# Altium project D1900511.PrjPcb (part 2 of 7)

## Sheet ISC_C3_SH3.SchDoc: ISC System Wiring Diagram
size B; DrawnBy: Filiberto Clara; Engineer: Filiberto Clara; Organization: LIGO Laboratory; Address1: California Institute of Technology; Address2: Massachusetts Institute of Technology; DocumentNumber: D1900511; Revision: V11; SheetNumber: 7; SheetTotal: 39
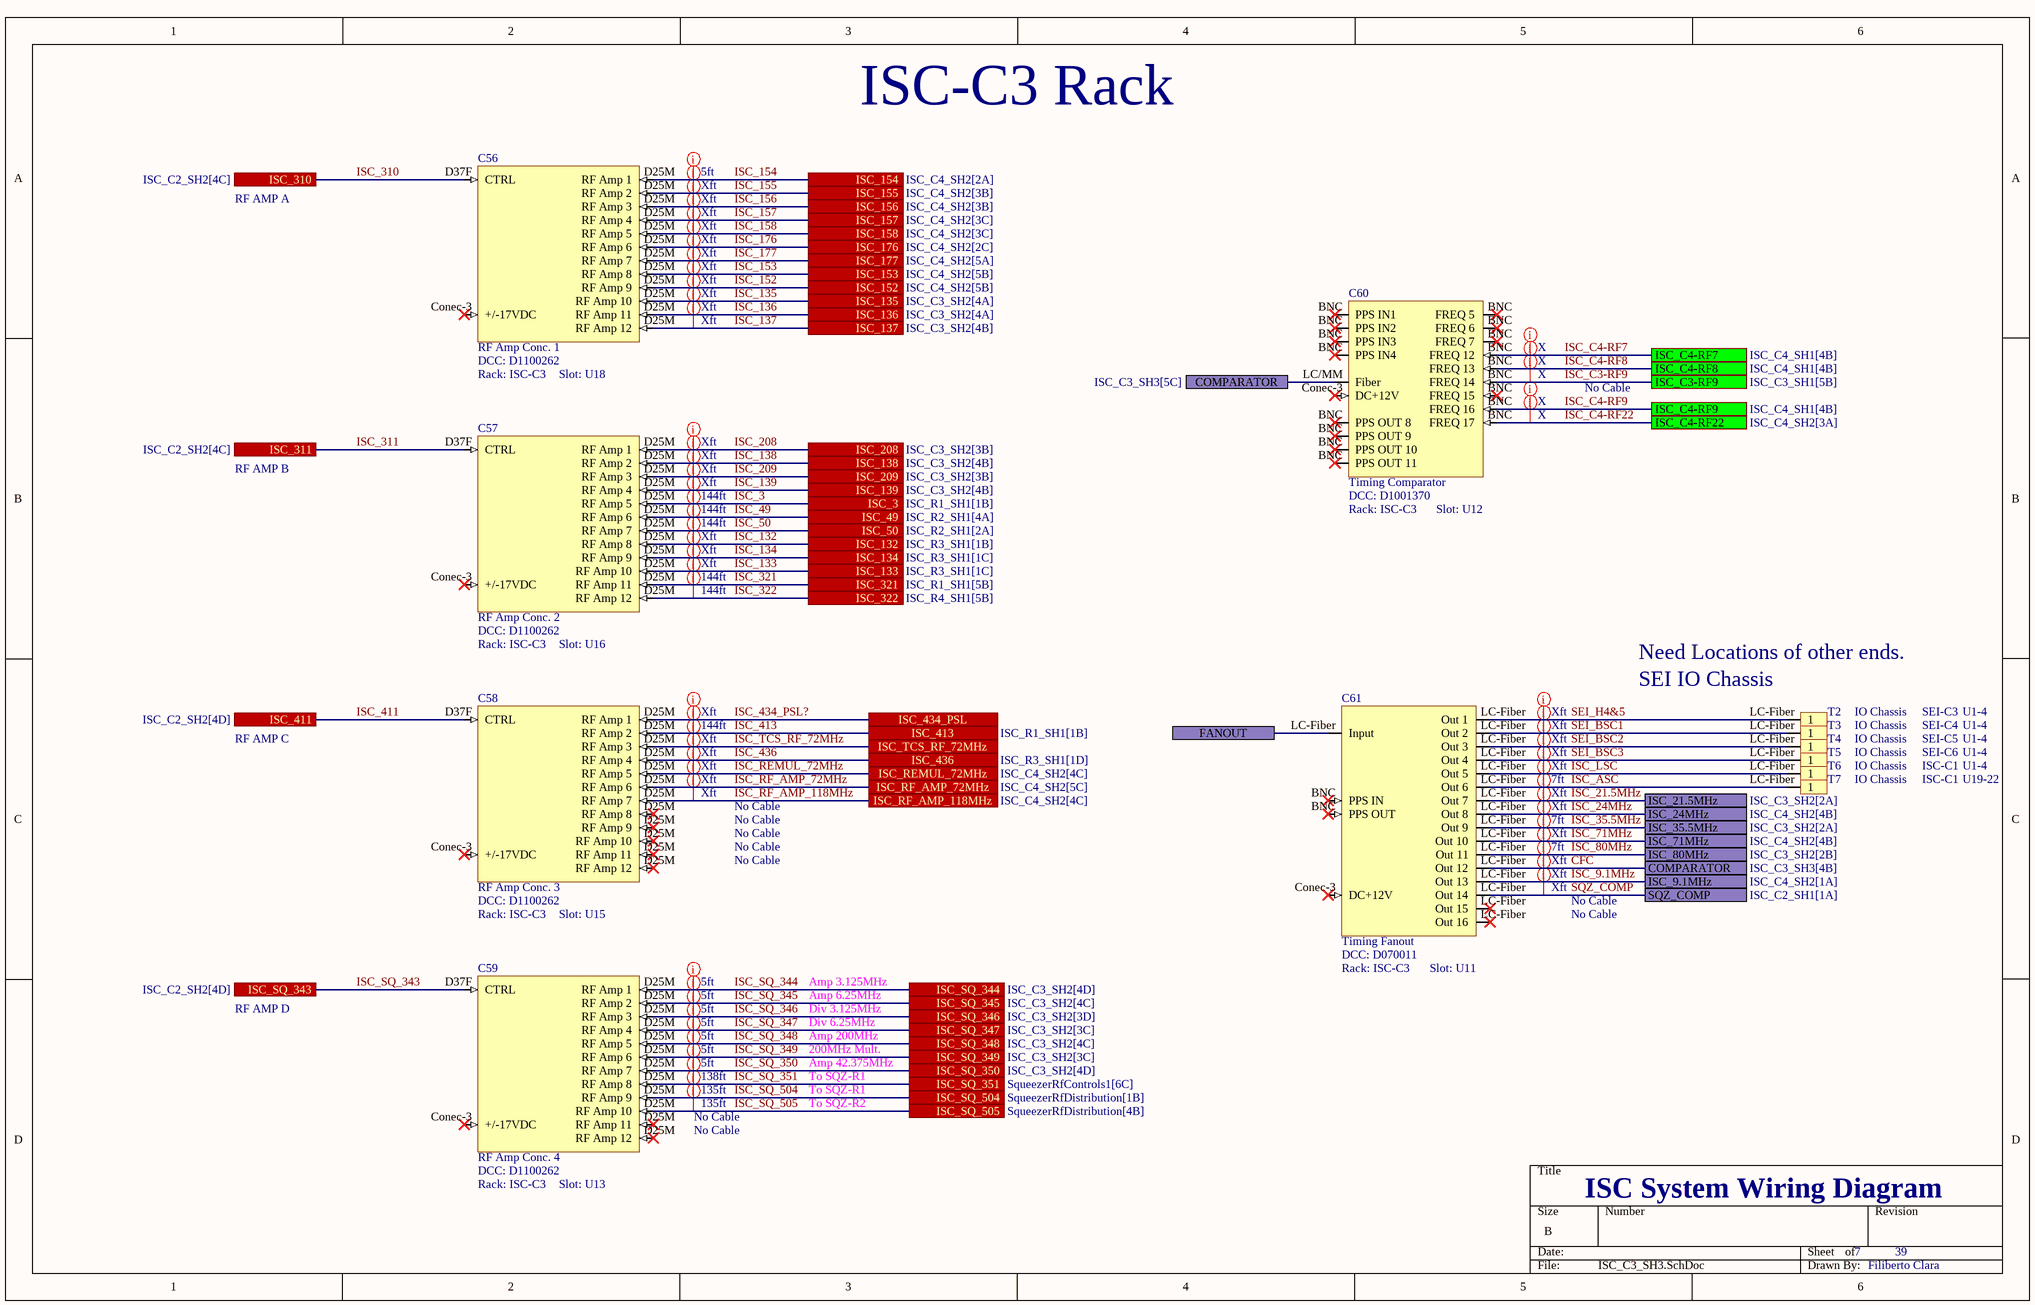
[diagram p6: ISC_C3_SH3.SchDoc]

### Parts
C56  RF Amp Conc. 1  DCC: D1100262  Rack: ISC-C3  Slot: U18
C57  RF Amp Conc. 2  DCC: D1100262  Rack: ISC-C3  Slot: U16
C58  RF Amp Conc. 3  DCC: D1100262  Rack: ISC-C3  Slot: U15
C59  RF Amp Conc. 4  DCC: D1100262  Rack: ISC-C3  Slot: U13
C60  Timing Comparator  DCC: D1001370  Rack: ISC-C3  Slot: U12
C61  Timing Fanout  DCC: D070011  Rack: ISC-C3  Slot: U11
T2  IO Chassis  Rack: SEI-C3  Slot: U1-4
T3  IO Chassis  Rack: SEI-C4  Slot: U1-4
T4  IO Chassis  Rack: SEI-C5  Slot: U1-4
T5  IO Chassis  Rack: SEI-C6  Slot: U1-4
T6  IO Chassis  Rack: ISC-C1  Slot: U1-4
T7  IO Chassis  Rack: ISC-C1  Slot: U19-22

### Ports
COMPARATOR (see ISC_C3_SH3[4B]), COMPARATOR (see ISC_C3_SH3[5C]), FANOUT, ISC_3 (see ISC_R1_SH1[1B]), ISC_9.1MHz (see ISC_C4_SH2[1A]), ISC_21.5MHz (see ISC_C3_SH2[2A]), ISC_24MHz (see ISC_C4_SH2[4B]), ISC_35.5MHz (see ISC_C3_SH2[2A]), ISC_49 (see ISC_R2_SH1[4A]), ISC_50 (see ISC_R2_SH1[2A]), ISC_71MHz (see ISC_C4_SH2[4B]), ISC_80MHz (see ISC_C3_SH2[2B]), ISC_132 (see ISC_R3_SH1[1B]), ISC_133 (see ISC_R3_SH1[1C]), ISC_134 (see ISC_R3_SH1[1C]), ISC_135 (see ISC_C3_SH2[4A]), ISC_136 (see ISC_C3_SH2[4A]), ISC_137 (see ISC_C3_SH2[4B]), ISC_138 (see ISC_C3_SH2[4B]), ISC_139 (see ISC_C3_SH2[4B]), ISC_152 (see ISC_C4_SH2[5B]), ISC_153 (see ISC_C4_SH2[5B]), ISC_154 (see ISC_C4_SH2[2A]), ISC_155 (see ISC_C4_SH2[3B]), ISC_156 (see ISC_C4_SH2[3B]), ISC_157 (see ISC_C4_SH2[3C]), ISC_158 (see ISC_C4_SH2[3C]), ISC_176 (see ISC_C4_SH2[2C]), ISC_177 (see ISC_C4_SH2[5A]), ISC_208 (see ISC_C3_SH2[3B]), ISC_209 (see ISC_C3_SH2[3B]), ISC_310 (see ISC_C2_SH2[4C]), ISC_311 (see ISC_C2_SH2[4C]), ISC_321 (see ISC_R1_SH1[5B]), ISC_322 (see ISC_R4_SH1[5B]), ISC_411 (see ISC_C2_SH2[4D]), ISC_413 (see ISC_R1_SH1[1B]), ISC_434_PSL, ISC_436 (see ISC_R3_SH1[1D]), ISC_C3-RF9 (see ISC_C3_SH1[5B]), ISC_C4-RF7 (see ISC_C4_SH1[4B]), ISC_C4-RF8 (see ISC_C4_SH1[4B]), ISC_C4-RF9 (see ISC_C4_SH1[4B]), ISC_C4-RF22 (see ISC_C4_SH2[3A]), ISC_REMUL_72MHz (see ISC_C4_SH2[4C]), ISC_RF_AMP_72MHz (see ISC_C4_SH2[5C]), ISC_RF_AMP_118MHz (see ISC_C4_SH2[4C]), ISC_SQ_343 (see ISC_C2_SH2[4D]), ISC_SQ_344 (see ISC_C3_SH2[4D]), ISC_SQ_345 (see ISC_C3_SH2[4C]), ISC_SQ_346 (see ISC_C3_SH2[3D]), ISC_SQ_347 (see ISC_C3_SH2[3C]), ISC_SQ_348 (see ISC_C3_SH2[4C]), ISC_SQ_349 (see ISC_C3_SH2[3C]), ISC_SQ_350 (see ISC_C3_SH2[4D]), ISC_SQ_351 (see SqueezerRfControls1[6C]), ISC_SQ_504 (see SqueezerRfDistribution[1B]), ISC_SQ_505 (see SqueezerRfDistribution[4B]), ISC_TCS_RF_72MHz, SQZ_COMP (see ISC_C2_SH1[1A])

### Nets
CFC: C60.LC/MM(Fiber) C61.LC-Fiber(Out_12) ; port COMPARATOR
ISC_3: C57.D25M(RF_Amp_5) ; port ISC_3
ISC_9.1MHz: C61.LC-Fiber(Out_13) ; port ISC_9.1MHz
ISC_21.5MHz: C61.LC-Fiber(Out_7) ; port ISC_21.5MHz
ISC_24MHz: C61.LC-Fiber(Out_8) ; port ISC_24MHz
ISC_35.5MHz: C61.LC-Fiber(Out_9) ; port ISC_35.5MHz
ISC_49: C57.D25M(RF_Amp_6) ; port ISC_49
ISC_50: C57.D25M(RF_Amp_7) ; port ISC_50
ISC_71MHz: C61.LC-Fiber(Out_10) ; port ISC_71MHz
ISC_80MHz: C61.LC-Fiber(Out_11) ; port ISC_80MHz
ISC_132: C57.D25M(RF_Amp_8) ; port ISC_132
ISC_133: C57.D25M(RF_Amp_10) ; port ISC_133
ISC_134: C57.D25M(RF_Amp_9) ; port ISC_134
ISC_135: C56.D25M(RF_Amp_10) ; port ISC_135
ISC_136: C56.D25M(RF_Amp_11) ; port ISC_136
ISC_137: C56.D25M(RF_Amp_12) ; port ISC_137
ISC_138: C57.D25M(RF_Amp_2) ; port ISC_138
ISC_139: C57.D25M(RF_Amp_4) ; port ISC_139
ISC_152: C56.D25M(RF_Amp_9) ; port ISC_152
ISC_153: C56.D25M(RF_Amp_8) ; port ISC_153
ISC_154: C56.D25M(RF_Amp_1) ; port ISC_154
ISC_155: C56.D25M(RF_Amp_2) ; port ISC_155
ISC_156: C56.D25M(RF_Amp_3) ; port ISC_156
ISC_157: C56.D25M(RF_Amp_4) ; port ISC_157
ISC_158: C56.D25M(RF_Amp_5) ; port ISC_158
ISC_176: C56.D25M(RF_Amp_6) ; port ISC_176
ISC_177: C56.D25M(RF_Amp_7) ; port ISC_177
ISC_208: C57.D25M(RF_Amp_1) ; port ISC_208
ISC_209: C57.D25M(RF_Amp_3) ; port ISC_209
ISC_310: C56.D37F(CTRL) ; port ISC_310
ISC_311: C57.D37F(CTRL) ; port ISC_311
ISC_321: C57.D25M(RF_Amp_11) ; port ISC_321
ISC_322: C57.D25M(RF_Amp_12) ; port ISC_322
ISC_411: C58.D37F(CTRL) ; port ISC_411
ISC_413: C58.D25M(RF_Amp_2) ; port ISC_413
ISC_434_PSL?: C58.D25M(RF_Amp_1) ; port ISC_434_PSL
ISC_436: C58.D25M(RF_Amp_4) ; port ISC_436
ISC_ASC: C61.LC-Fiber(Out_6) T7.LC-Fiber(1)
ISC_C3-RF9: C60.BNC(FREQ_14) ; port ISC_C3-RF9
ISC_C4-RF7: C60.BNC(PPS_IN1) ; port ISC_C4-RF7
ISC_C4-RF8: C60.BNC(FREQ_13) ; port ISC_C4-RF8
ISC_C4-RF9: C60.BNC(FREQ_16) ; port ISC_C4-RF9
ISC_C4-RF22: C60.BNC(FREQ_17) ; port ISC_C4-RF22
ISC_LSC: C61.LC-Fiber(Out_5) T6.LC-Fiber(1)
ISC_REMUL_72MHz: C58.D25M(RF_Amp_5) ; port ISC_REMUL_72MHz
ISC_RF_AMP_72MHz: C58.D25M(RF_Amp_6) ; port ISC_RF_AMP_72MHz
ISC_RF_AMP_118MHz: C58.D25M(RF_Amp_7) ; port ISC_RF_AMP_118MHz
ISC_SQ_343: C59.D37F(CTRL) ; port ISC_SQ_343
ISC_SQ_344: C59.D25M(RF_Amp_1) ; port ISC_SQ_344
ISC_SQ_345: C59.D25M(RF_Amp_2) ; port ISC_SQ_345
ISC_SQ_346: C59.D25M(RF_Amp_3) ; port ISC_SQ_346
ISC_SQ_347: C59.D25M(RF_Amp_4) ; port ISC_SQ_347
ISC_SQ_348: C59.D25M(RF_Amp_5) ; port ISC_SQ_348
ISC_SQ_349: C59.D25M(RF_Amp_6) ; port ISC_SQ_349
ISC_SQ_350: C59.D25M(RF_Amp_7) ; port ISC_SQ_350
ISC_SQ_351: C59.D25M(RF_Amp_8) ; port ISC_SQ_351
ISC_SQ_504: C59.D25M(RF_Amp_9) ; port ISC_SQ_504
ISC_SQ_505: C59.D25M(RF_Amp_10) ; port ISC_SQ_505
ISC_TCS_RF_72MHz: C58.D25M(RF_Amp_3) ; port ISC_TCS_RF_72MHz
SEI_BSC1: C61.LC-Fiber(Out_2) T3.LC-Fiber(1)
SEI_BSC2: C61.LC-Fiber(Out_3) T4.LC-Fiber(1)
SEI_BSC3: C61.LC-Fiber(Out_4) T5.LC-Fiber(1)
SEI_H4&5: C61.LC-Fiber(Out_1) T2.LC-Fiber(1)
SQZ_COMP: C61.LC-Fiber(Out_14) ; port SQZ_COMP
NetC61_LC-Fiber: C61.LC-Fiber(Input) ; port FANOUT

Not connected (* = marked no-connect by the designer): C56 Conec-3(+/-17VDC)*; C57 Conec-3(+/-17VDC)*; C58 Conec-3(+/-17VDC)*; C59 Conec-3(+/-17VDC)*; C60 Conec-3(DC+12V)*; C61 BNC(PPS_IN)* Conec-3(DC+12V)*

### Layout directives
Length: 5ft: ISC_154, ISC_SQ_344, ISC_SQ_345, ISC_SQ_346, ISC_SQ_347, ISC_SQ_348, ISC_SQ_349, ISC_SQ_350
Length: 138ft: ISC_SQ_351
Length: Xft: CFC, ISC_9.1MHz, ISC_21.5MHz, ISC_24MHz, ISC_71MHz, ISC_132, ISC_133, ISC_134, ISC_135, ISC_136, ISC_137, ISC_138, ISC_139, ISC_152, ISC_153, ISC_155, ISC_156, ISC_157, ISC_158, ISC_176, ISC_177, ISC_208, ISC_209, ISC_434_PSL?, ISC_436, ISC_LSC, ISC_REMUL_72MHz, ISC_RF_AMP_72MHz, ISC_RF_AMP_118MHz, ISC_TCS_RF_72MHz, SEI_BSC1, SEI_BSC2, SEI_BSC3, SEI_H4&5, SQZ_COMP
Length: 144ft: ISC_3, ISC_49, ISC_50, ISC_321, ISC_322, ISC_413
Length: 7ft: ISC_35.5MHz, ISC_80MHz, ISC_ASC
Length: X: ISC_C3-RF9, ISC_C4-RF7, ISC_C4-RF8, ISC_C4-RF9, ISC_C4-RF22
Length: 135ft: ISC_SQ_504, ISC_SQ_505

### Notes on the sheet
- ISC-C3 Rack
- RF AMP A
- No Cable
- RF AMP B
- SEI IO Chassis
- Need Locations of other ends.
- RF AMP C
- Amp 3.125MHz
- RF AMP D
- Amp 6.25MHz
- Div 3.125MHz
- Div 6.25MHz
- Amp 200MHz
- 200MHz Mult.
- Amp 42.375MHz
- To SQZ-R1
- To SQZ-R2

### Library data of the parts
C56-C59 = RF Amp Conc.: Serial: Sxxxxxxx; System: ISC
C60 = Timing Comparator: Serial: Sxxxxxxx; System: ISC
C61 = Timing Fanout: Serial: Sxxxxxxx; System: ISC
T2-T7 = Placeholder: Serial: Sxxxxxxx; System: ISC; DCC: tbd

## Sheet ISC_C4_SH1.SchDoc: ISC System Wiring Diagram
size B; DrawnBy: Filiberto Clara; Engineer: Filiberto Clara; Organization: LIGO Laboratory; Address1: California Institute of Technology; Address2: Massachusetts Institute of Technology; DocumentNumber: D1900511; Revision: V11; SheetNumber: 8; SheetTotal: 39
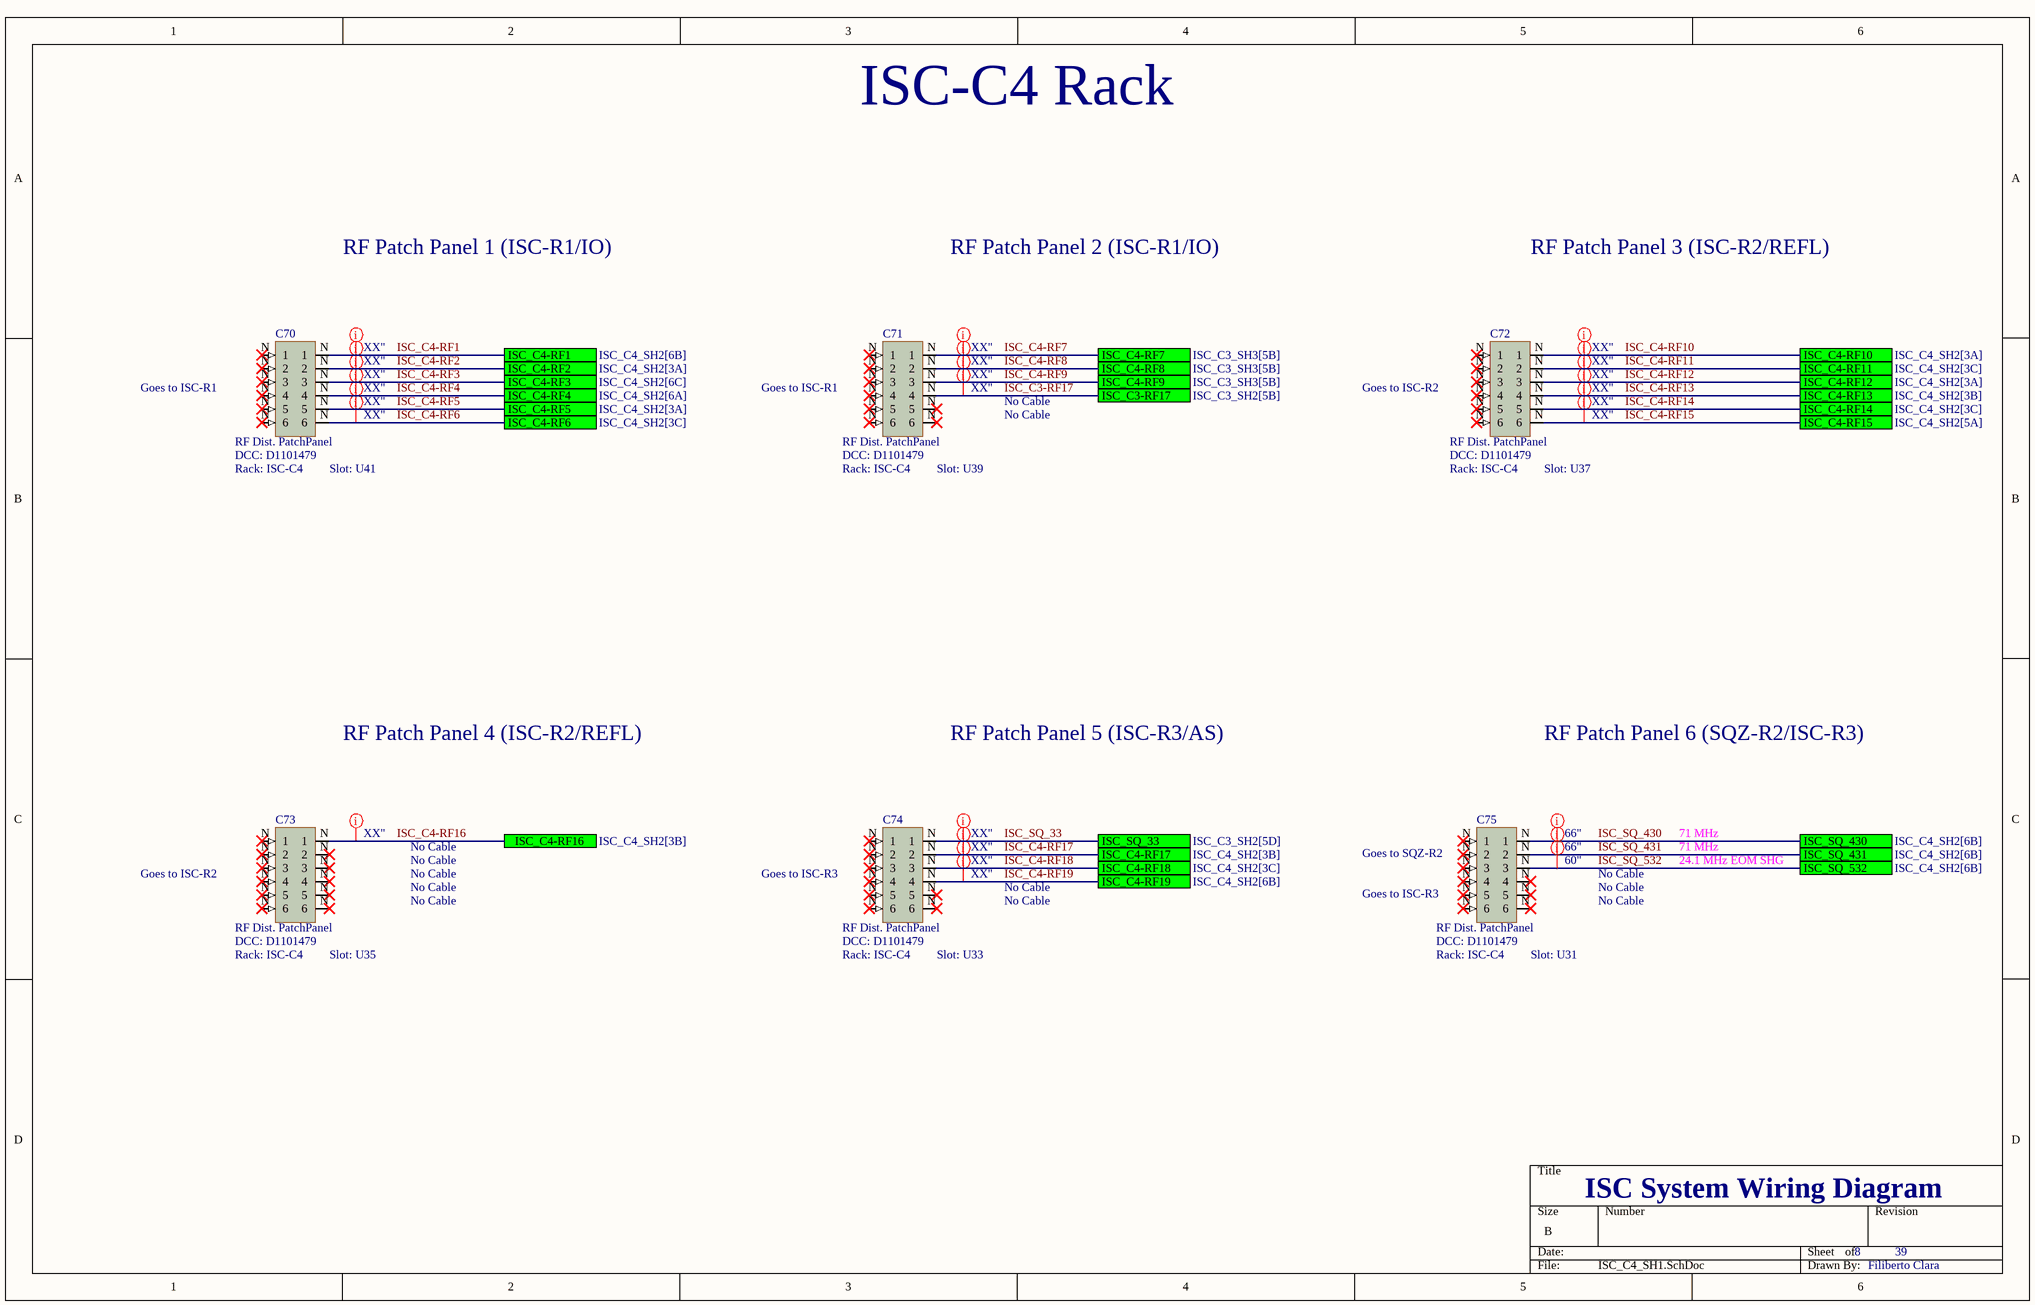
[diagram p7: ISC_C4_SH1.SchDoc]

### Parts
C70  RF Dist. PatchPanel  DCC: D1101479  Rack: ISC-C4  Slot: U41
C71  RF Dist. PatchPanel  DCC: D1101479  Rack: ISC-C4  Slot: U39
C72  RF Dist. PatchPanel  DCC: D1101479  Rack: ISC-C4  Slot: U37
C73  RF Dist. PatchPanel  DCC: D1101479  Rack: ISC-C4  Slot: U35
C74  RF Dist. PatchPanel  DCC: D1101479  Rack: ISC-C4  Slot: U33
C75  RF Dist. PatchPanel  DCC: D1101479  Rack: ISC-C4  Slot: U31

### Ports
ISC_C3-RF17 (see ISC_C3_SH2[5B]), ISC_C4-RF1 (see ISC_C4_SH2[6B]), ISC_C4-RF2 (see ISC_C4_SH2[3A]), ISC_C4-RF3 (see ISC_C4_SH2[6C]), ISC_C4-RF4 (see ISC_C4_SH2[6A]), ISC_C4-RF5 (see ISC_C4_SH2[3A]), ISC_C4-RF6 (see ISC_C4_SH2[3C]), ISC_C4-RF7 (see ISC_C3_SH3[5B]), ISC_C4-RF8 (see ISC_C3_SH3[5B]), ISC_C4-RF9 (see ISC_C3_SH3[5B]), ISC_C4-RF10 (see ISC_C4_SH2[3A]), ISC_C4-RF11 (see ISC_C4_SH2[3C]), ISC_C4-RF12 (see ISC_C4_SH2[3A]), ISC_C4-RF13 (see ISC_C4_SH2[3B]), ISC_C4-RF14 (see ISC_C4_SH2[3C]), ISC_C4-RF15 (see ISC_C4_SH2[5A]), ISC_C4-RF16 (see ISC_C4_SH2[3B]), ISC_C4-RF17 (see ISC_C4_SH2[3B]), ISC_C4-RF18 (see ISC_C4_SH2[3C]), ISC_C4-RF19 (see ISC_C4_SH2[6B]), ISC_SQ_33 (see ISC_C3_SH2[5D]), ISC_SQ_430 (see ISC_C4_SH2[6B]), ISC_SQ_431 (see ISC_C4_SH2[6B]), ISC_SQ_532 (see ISC_C4_SH2[6B])

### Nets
ISC_C3-RF17: C71.N(4) ; port ISC_C3-RF17
ISC_C4-RF1: C70.N(1) ; port ISC_C4-RF1
ISC_C4-RF2: C70.N(2) ; port ISC_C4-RF2
ISC_C4-RF3: C70.N(3) ; port ISC_C4-RF3
ISC_C4-RF4: C70.N(4) ; port ISC_C4-RF4
ISC_C4-RF5: C70.N(5) ; port ISC_C4-RF5
ISC_C4-RF6: C70.N(6) ; port ISC_C4-RF6
ISC_C4-RF7: C71.N(1) ; port ISC_C4-RF7
ISC_C4-RF8: C71.N(2) ; port ISC_C4-RF8
ISC_C4-RF9: C71.N(3) ; port ISC_C4-RF9
ISC_C4-RF10: C72.N(1) ; port ISC_C4-RF10
ISC_C4-RF11: C72.N(2) ; port ISC_C4-RF11
ISC_C4-RF12: C72.N(3) ; port ISC_C4-RF12
ISC_C4-RF13: C72.N(4) ; port ISC_C4-RF13
ISC_C4-RF14: C72.N(5) ; port ISC_C4-RF14
ISC_C4-RF15: C72.N(6) ; port ISC_C4-RF15
ISC_C4-RF16: C73.N(1) ; port ISC_C4-RF16
ISC_C4-RF17: C74.N(2) ; port ISC_C4-RF17
ISC_C4-RF18: C74.N(3) ; port ISC_C4-RF18
ISC_C4-RF19: C74.N(4) ; port ISC_C4-RF19
ISC_SQ_33: C74.N(1) ; port ISC_SQ_33
ISC_SQ_430: C75.N(1) ; port ISC_SQ_430
ISC_SQ_431: C75.N(2) ; port ISC_SQ_431
ISC_SQ_532: C75.N(3) ; port ISC_SQ_532

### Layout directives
Length: XX": ISC_C3-RF17, ISC_C4-RF1, ISC_C4-RF2, ISC_C4-RF3, ISC_C4-RF4, ISC_C4-RF5, ISC_C4-RF6, ISC_C4-RF7, ISC_C4-RF8, ISC_C4-RF9, ISC_C4-RF10, ISC_C4-RF11, ISC_C4-RF12, ISC_C4-RF13, ISC_C4-RF14, ISC_C4-RF15, ISC_C4-RF16, ISC_C4-RF17, ISC_C4-RF18, ISC_C4-RF19, ISC_SQ_33
Length: 66": ISC_SQ_430, ISC_SQ_431
Length: 60": ISC_SQ_532

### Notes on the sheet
- ISC-C4 Rack
- RF Patch Panel 1 (ISC-R1/IO)
- RF Patch Panel 2 (ISC-R1/IO)
- RF Patch Panel 3 (ISC-R2/REFL)
- (near C70) Goes to ISC-R1
- (near C71) Goes to ISC-R1
- No Cable
- (near C72) Goes to ISC-R2
- RF Patch Panel 4 (ISC-R2/REFL)
- RF Patch Panel 5 (ISC-R3/AS)
- RF Patch Panel 6 (SQZ-R2/ISC-R3)
- 71 MHz
- (near C73) Goes to ISC-R2
- (near C74) Goes to ISC-R3
- (near C75) Goes to SQZ-R2
- (near C75) Goes to ISC-R3
- 24.1 MHz EOM SHG

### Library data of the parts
C70-C75 = RF Dist. PatchPanel: Serial: Sxxxxxxx; System: ISC

## Sheet ISC_C4_SH2.SchDoc: ISC System Wiring Diagram
size C; DrawnBy: Filiberto Clara; Engineer: Filiberto Clara; Organization: LIGO Laboratory; Address1: California Institute of Technology; Address2: Massachusetts Institute of Technology; DocumentNumber: D1900511; Revision: V11; SheetNumber: 9; SheetTotal: 39
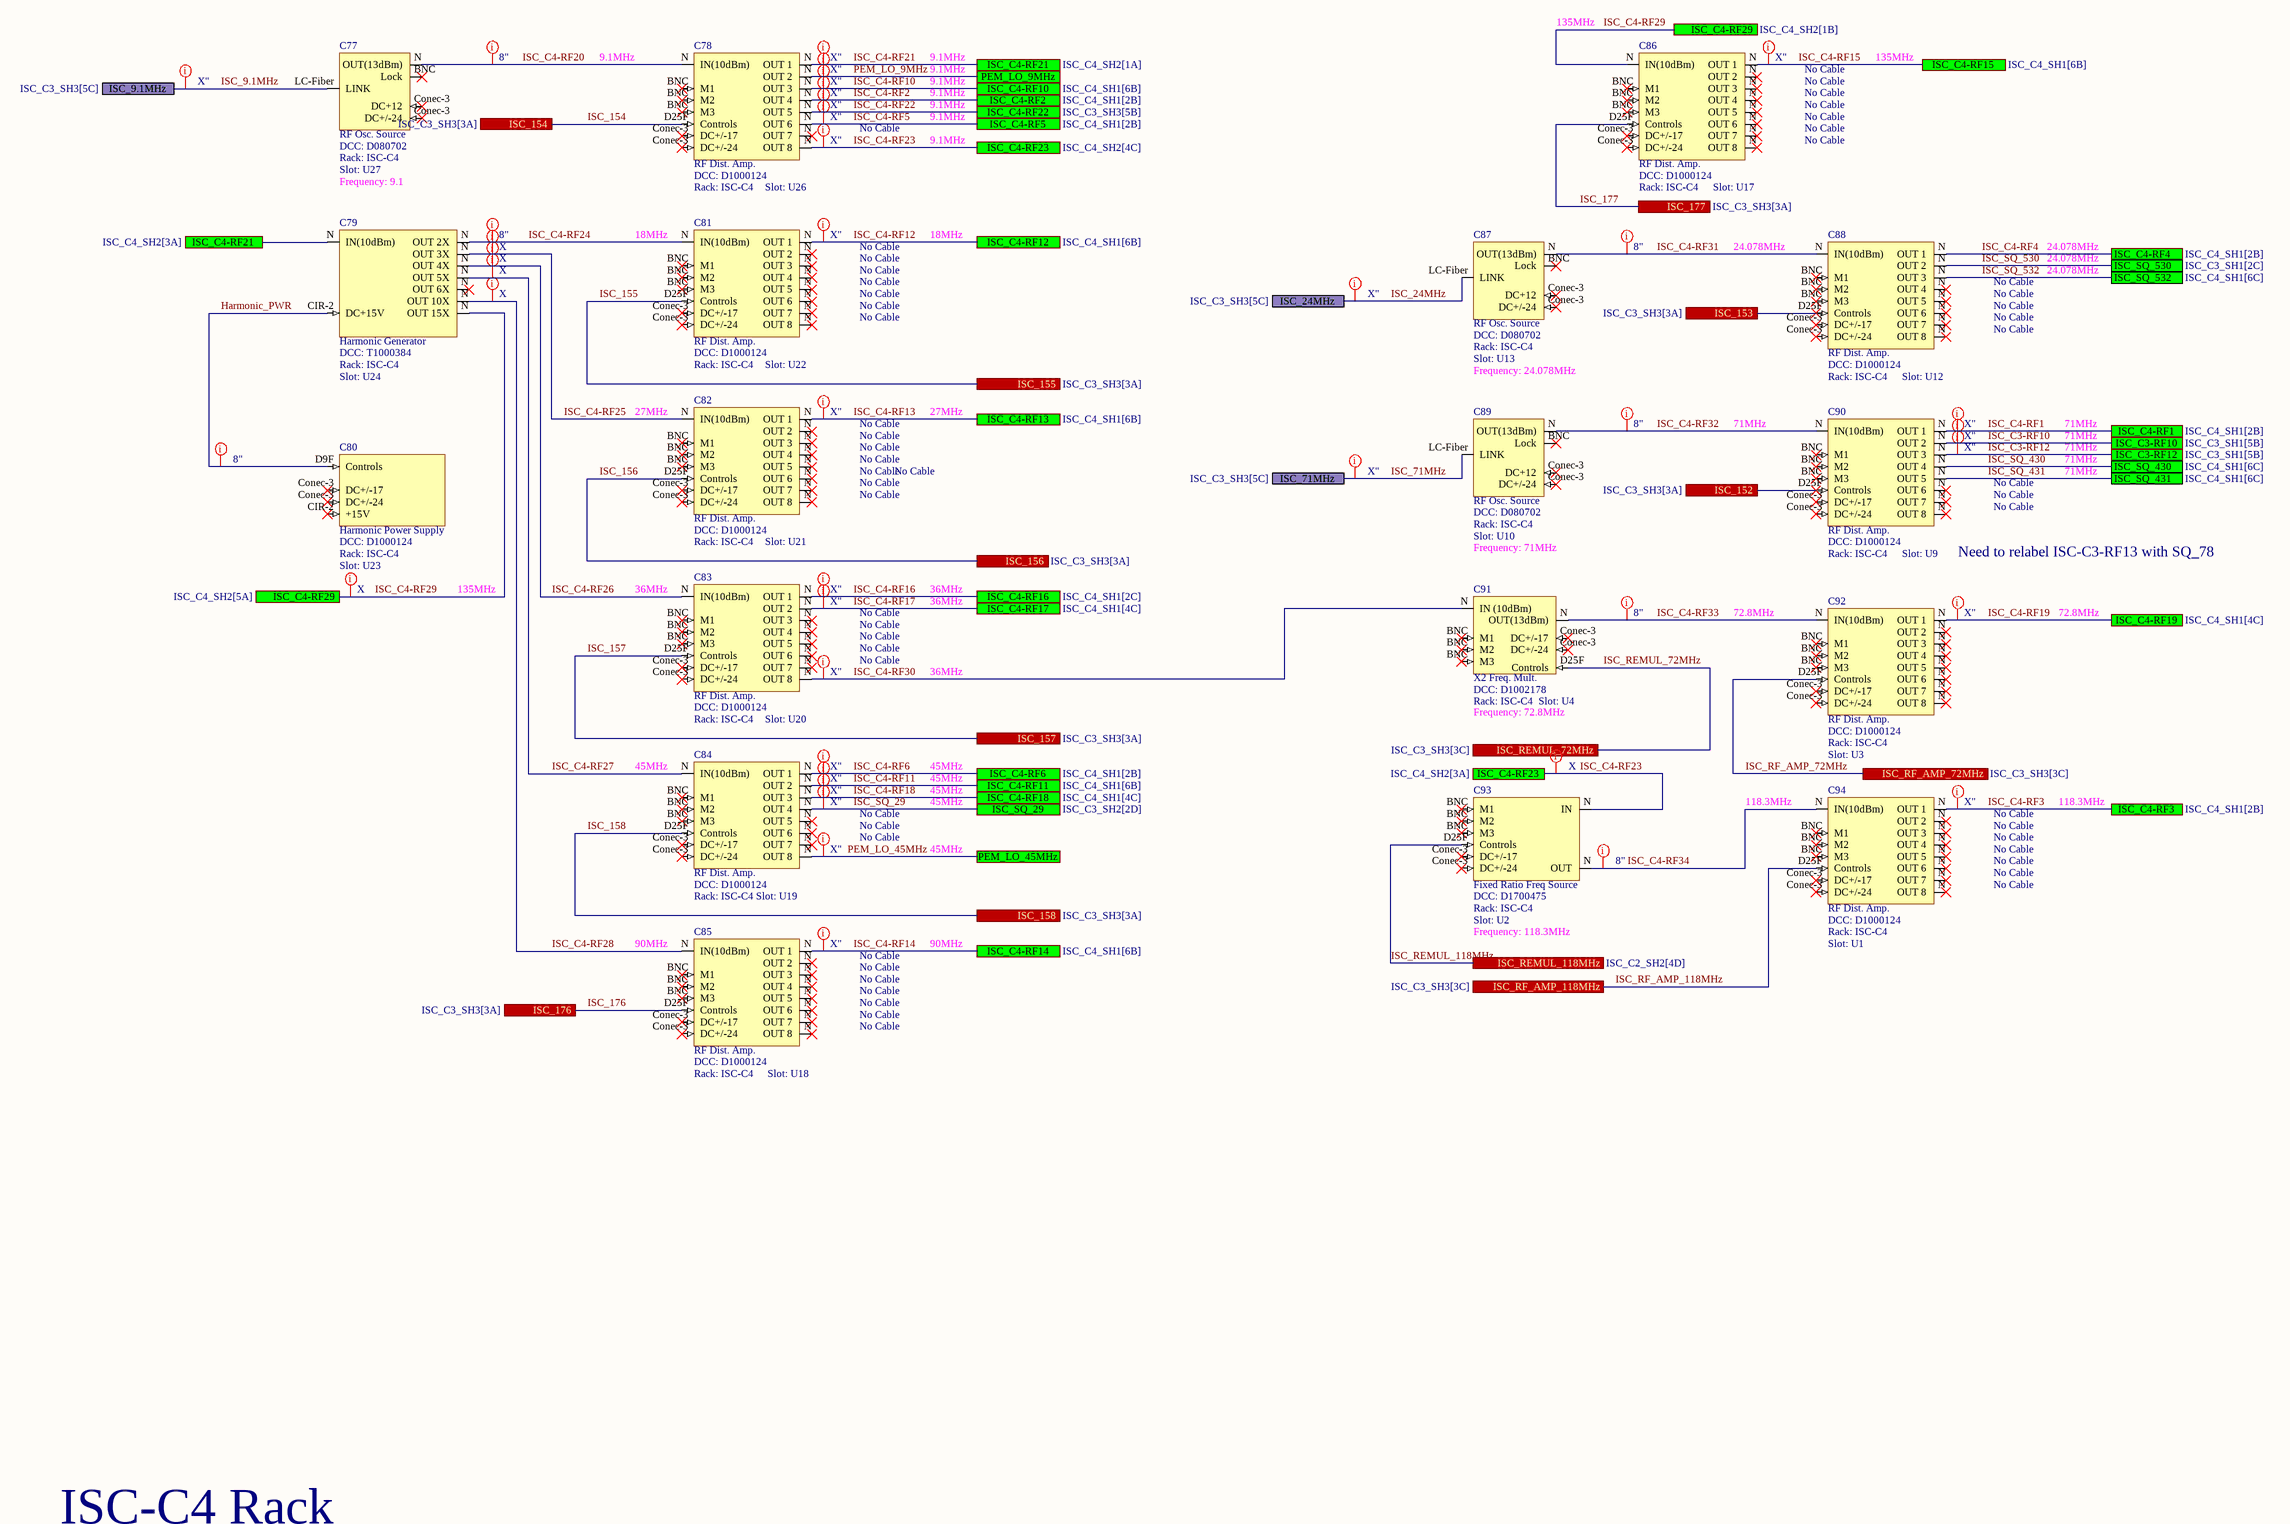
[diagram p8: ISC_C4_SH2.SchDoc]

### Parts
C77  RF Osc. Source  DCC: D080702  Rack: ISC-C4  Slot: U27  Frequency: 9.1
C78  RF Dist. Amp.  DCC: D1000124  Rack: ISC-C4  Slot: U26
C79  Harmonic Generator  DCC: T1000384  Rack: ISC-C4  Slot: U24
C80  Harmonic Power Supply  DCC: D1000124  Rack: ISC-C4  Slot: U23
C81  RF Dist. Amp.  DCC: D1000124  Rack: ISC-C4  Slot: U22
C82  RF Dist. Amp.  DCC: D1000124  Rack: ISC-C4  Slot: U21
C83  RF Dist. Amp.  DCC: D1000124  Rack: ISC-C4  Slot: U20
C84  RF Dist. Amp.  DCC: D1000124  Rack: ISC-C4  Slot: U19
C85  RF Dist. Amp.  DCC: D1000124  Rack: ISC-C4  Slot: U18
C86  RF Dist. Amp.  DCC: D1000124  Rack: ISC-C4  Slot: U17
C87  RF Osc. Source  DCC: D080702  Rack: ISC-C4  Slot: U13  Frequency: 24.078MHz
C88  RF Dist. Amp.  DCC: D1000124  Rack: ISC-C4  Slot: U12
C89  RF Osc. Source  DCC: D080702  Rack: ISC-C4  Slot: U10  Frequency: 71MHz
C90  RF Dist. Amp.  DCC: D1000124  Rack: ISC-C4  Slot: U9
C91  X2 Freq. Mult.  DCC: D1002178  Rack: ISC-C4  Slot: U4  Frequency: 72.8MHz
C92  RF Dist. Amp.  DCC: D1000124  Rack: ISC-C4  Slot: U3
C93  Fixed Ratio Freq Source  DCC: D1700475  Rack: ISC-C4  Slot: U2  Frequency: 118.3MHz
C94  RF Dist. Amp.  DCC: D1000124  Rack: ISC-C4  Slot: U1

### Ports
ISC_9.1MHz (see ISC_C3_SH3[5C]), ISC_24MHz (see ISC_C3_SH3[5C]), ISC_71MHz (see ISC_C3_SH3[5C]), ISC_152 (see ISC_C3_SH3[3A]), ISC_153 (see ISC_C3_SH3[3A]), ISC_154 (see ISC_C3_SH3[3A]), ISC_155 (see ISC_C3_SH3[3A]), ISC_156 (see ISC_C3_SH3[3A]), ISC_157 (see ISC_C3_SH3[3A]), ISC_158 (see ISC_C3_SH3[3A]), ISC_176 (see ISC_C3_SH3[3A]), ISC_177 (see ISC_C3_SH3[3A]), ISC_C3-RF10 (see ISC_C3_SH1[5B]), ISC_C3-RF12 (see ISC_C3_SH1[5B]), ISC_C4-RF1 (see ISC_C4_SH1[2B]), ISC_C4-RF2 (see ISC_C4_SH1[2B]), ISC_C4-RF3 (see ISC_C4_SH1[2B]), ISC_C4-RF4 (see ISC_C4_SH1[2B]), ISC_C4-RF5 (see ISC_C4_SH1[2B]), ISC_C4-RF6 (see ISC_C4_SH1[2B]), ISC_C4-RF10 (see ISC_C4_SH1[6B]), ISC_C4-RF11 (see ISC_C4_SH1[6B]), ISC_C4-RF12 (see ISC_C4_SH1[6B]), ISC_C4-RF13 (see ISC_C4_SH1[6B]), ISC_C4-RF14 (see ISC_C4_SH1[6B]), ISC_C4-RF15 (see ISC_C4_SH1[6B]), ISC_C4-RF16 (see ISC_C4_SH1[2C]), ISC_C4-RF17 (see ISC_C4_SH1[4C]), ISC_C4-RF18 (see ISC_C4_SH1[4C]), ISC_C4-RF19 (see ISC_C4_SH1[4C]), ISC_C4-RF21 (see ISC_C4_SH2[1A]), ISC_C4-RF21 (see ISC_C4_SH2[3A]), ISC_C4-RF22 (see ISC_C3_SH3[5B]), ISC_C4-RF23 (see ISC_C4_SH2[3A]), ISC_C4-RF23 (see ISC_C4_SH2[4C]), ISC_C4-RF29 (see ISC_C4_SH2[1B]), ISC_C4-RF29 (see ISC_C4_SH2[5A]), ISC_REMUL_72MHz (see ISC_C3_SH3[3C]), ISC_REMUL_118MHz (see ISC_C2_SH2[4D]), ISC_RF_AMP_72MHz (see ISC_C3_SH3[3C]), ISC_RF_AMP_118MHz (see ISC_C3_SH3[3C]), ISC_SQ_29 (see ISC_C3_SH2[2D]), ISC_SQ_430 (see ISC_C4_SH1[6C]), ISC_SQ_431 (see ISC_C4_SH1[6C]), ISC_SQ_530 (see ISC_C3_SH1[2C]), ISC_SQ_532 (see ISC_C4_SH1[6C]), PEM_LO_9MHz, PEM_LO_45MHz

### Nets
Harmonic_PWR: C79.CIR-2(DC+15V) C80.D9F(Controls)
ISC_9.1MHz: C77.LC-Fiber(LINK) ; port ISC_9.1MHz
ISC_24MHz: C87.LC-Fiber(LINK) ; port ISC_24MHz
ISC_71MHz: C89.LC-Fiber(LINK) ; port ISC_71MHz
ISC_152: C90.D25F(Controls) ; port ISC_152
ISC_153: C88.D25F(Controls) ; port ISC_153
ISC_154: C78.D25F(Controls) ; port ISC_154
ISC_155: C81.D25F(Controls) ; port ISC_155
ISC_156: C82.D25F(Controls) ; port ISC_156
ISC_157: C83.D25F(Controls) ; port ISC_157
ISC_158: C84.D25F(Controls) ; port ISC_158
ISC_176: C85.D25F(Controls) ; port ISC_176
ISC_177: C86.D25F(Controls) ; port ISC_177
ISC_C3-RF10: C90.N(OUT_2) ; port ISC_C3-RF10
ISC_C3-RF12: C90.N(OUT_3) ; port ISC_C3-RF12
ISC_C4-RF1: C90.N(OUT_1) ; port ISC_C4-RF1
ISC_C4-RF2: C78.N(OUT_4) ; port ISC_C4-RF2
ISC_C4-RF3: C94.N(OUT_1) ; port ISC_C4-RF3
ISC_C4-RF4: C88.N(OUT_1) ; port ISC_C4-RF4
ISC_C4-RF5: C78.N(OUT_6) ; port ISC_C4-RF5
ISC_C4-RF6: C84.N(OUT_1) ; port ISC_C4-RF6
ISC_C4-RF10: C78.N(OUT_3) ; port ISC_C4-RF10
ISC_C4-RF11: C84.N(OUT_2) ; port ISC_C4-RF11
ISC_C4-RF12: C81.N(OUT_1) ; port ISC_C4-RF12
ISC_C4-RF13: C82.N(OUT_1) ; port ISC_C4-RF13
ISC_C4-RF14: C85.N(OUT_1) ; port ISC_C4-RF14
ISC_C4-RF15: C86.N(OUT_1) ; port ISC_C4-RF15
ISC_C4-RF16: C83.N(OUT_1) ; port ISC_C4-RF16
ISC_C4-RF17: C83.N(OUT_2) ; port ISC_C4-RF17
ISC_C4-RF18: C84.N(OUT_3) ; port ISC_C4-RF18
ISC_C4-RF19: C92.N(OUT_1) ; port ISC_C4-RF19
ISC_C4-RF20: C77.N(OUT(13dBm)) C78.N(IN(10dBm))
ISC_C4-RF21: C78.N(OUT_1) C79.N(IN(10dBm)) ; port ISC_C4-RF21
ISC_C4-RF22: C78.N(OUT_5) ; port ISC_C4-RF22
ISC_C4-RF23: C78.N(OUT_8) C93.N(IN) ; port ISC_C4-RF23
ISC_C4-RF24: C79.N(OUT_2X) C81.N(IN(10dBm))
ISC_C4-RF25: C79.N(OUT_3X) C82.N(IN(10dBm))
ISC_C4-RF26: C79.N(OUT_4X) C83.N(IN(10dBm))
ISC_C4-RF27: C79.N(OUT_5X) C84.N(IN(10dBm))
ISC_C4-RF28: C79.N(OUT_10X) C85.N(IN(10dBm))
ISC_C4-RF29: C79.N(OUT_15X) C86.N(IN(10dBm)) ; port ISC_C4-RF29
ISC_C4-RF30: C83.N(OUT_8) C91.N(IN_(10dBm))
ISC_C4-RF31: C87.N(OUT(13dBm)) C88.N(IN(10dBm))
ISC_C4-RF32: C89.N(OUT(13dBm)) C90.N(IN(10dBm))
ISC_C4-RF33: C91.N(OUT(13dBm)) C92.N(IN(10dBm))
ISC_C4-RF34: C93.N(OUT) C94.N(IN(10dBm))
ISC_REMUL_72MHz: C91.D25F(Controls) ; port ISC_REMUL_72MHz
ISC_REMUL_118MHz: C93.D25F(Controls) ; port ISC_REMUL_118MHz
ISC_RF_AMP_72MHz: C92.D25F(Controls) ; port ISC_RF_AMP_72MHz
ISC_RF_AMP_118MHz: C94.D25F(Controls) ; port ISC_RF_AMP_118MHz
ISC_SQ_29: C84.N(OUT_4) ; port ISC_SQ_29
ISC_SQ_430: C90.N(OUT_4) ; port ISC_SQ_430
ISC_SQ_431: C90.N(OUT_5) ; port ISC_SQ_431
ISC_SQ_530: C88.N(OUT_2) ; port ISC_SQ_530
ISC_SQ_532: C88.N(OUT_3) ; port ISC_SQ_532
PEM_LO_9MHz: C78.N(OUT_2) ; port PEM_LO_9MHz
PEM_LO_45MHz: C84.N(OUT_8) ; port PEM_LO_45MHz

Not connected (* = marked no-connect by the designer): C77 BNC(Lock)* Conec-3(DC+12)*; C78 BNC(M1)* Conec-3(DC+/-17)*; C80 CIR-2(+15V)* Conec-3(DC+/-17)*; C81 BNC(M1)* Conec-3(DC+/-17)*; C82 BNC(M1)* Conec-3(DC+/-17)*; C83 BNC(M1)* Conec-3(DC+/-17)*; C84 BNC(M1)* Conec-3(DC+/-17)*; C85 BNC(M1)* Conec-3(DC+/-17)*; C86 BNC(M1)* Conec-3(DC+/-17)*; C87 BNC(Lock)* Conec-3(DC+12)*; C88 BNC(M1)* Conec-3(DC+/-17)*; C89 BNC(Lock)* Conec-3(DC+12)*; C90 BNC(M1)* Conec-3(DC+/-17)*; C91 BNC(M1)* Conec-3(DC+/-17)*; C92 BNC(M1)* Conec-3(DC+/-17)*; C93 BNC(M1)* Conec-3(DC+/-17)*; C94 BNC(M1)* Conec-3(DC+/-17)*

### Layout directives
Length: 8": Harmonic_PWR, ISC_C4-RF20, ISC_C4-RF24, ISC_C4-RF31, ISC_C4-RF32, ISC_C4-RF33, ISC_C4-RF34
Length: X": ISC_9.1MHz, ISC_24MHz, ISC_71MHz, ISC_C3-RF10, ISC_C3-RF12, ISC_C4-RF1, ISC_C4-RF2, ISC_C4-RF3, ISC_C4-RF5, ISC_C4-RF6, ISC_C4-RF10, ISC_C4-RF11, ISC_C4-RF12, ISC_C4-RF13, ISC_C4-RF14, ISC_C4-RF15, ISC_C4-RF16, ISC_C4-RF17, ISC_C4-RF18, ISC_C4-RF19, ISC_C4-RF21, ISC_C4-RF22, ISC_C4-RF23, ISC_C4-RF30, ISC_SQ_29, PEM_LO_9MHz, PEM_LO_45MHz
Length: X: ISC_C4-RF23, ISC_C4-RF25, ISC_C4-RF26, ISC_C4-RF27, ISC_C4-RF28, ISC_C4-RF29

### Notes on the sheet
- 9.1MHz
- 135MHz
- No Cable
- (near C81) 18MHz
- 18MHz
- (near C88) 24.078MHz
- 24.078MHz
- (near C82) 27MHz
- 27MHz
- 71MHz
- (near C83) 36MHz
- 36MHz
- (near C90) Need to relabel ISC-C3-RF13 with SQ_78
- 72.8MHz
- (near C84) 45MHz
- 45MHz
- (near C94) 118.3MHz
- 118.3MHz
- (near C85) 90MHz
- 90MHz
- ISC-C4 Rack

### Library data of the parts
C77 C87 C89 = RF Osc. Source: Serial: Sxxxxxxx; System: ISC
C78 C81-C86 C88 C90 C92 C94 = RF Distribution Amplifier: Serial: Sxxxxxxx; System: ISC
C79 = Harmonic Generator: Serial: Sxxxxxxx; System: ISC
C80 = Harmonic Power Supply: Serial: Sxxxxxxx; System: ISC
C91 = X2 Freq. Mult.: Serial: Sxxxxxxx; System: ISC
C93 = Fixed Ratio Freq Source: Serial: Sxxxxxxx; System: ISC

## Sheet ISC_R1_SH1.SchDoc: ISC System Wiring Diagram
size C; DrawnBy: Filiberto Clara; Engineer: Filiberto Clara; Organization: LIGO Laboratory; Address1: California Institute of Technology; Address2: Massachusetts Institute of Technology; DocumentNumber: D1900511; Revision: V11; SheetNumber: 10; SheetTotal: 39
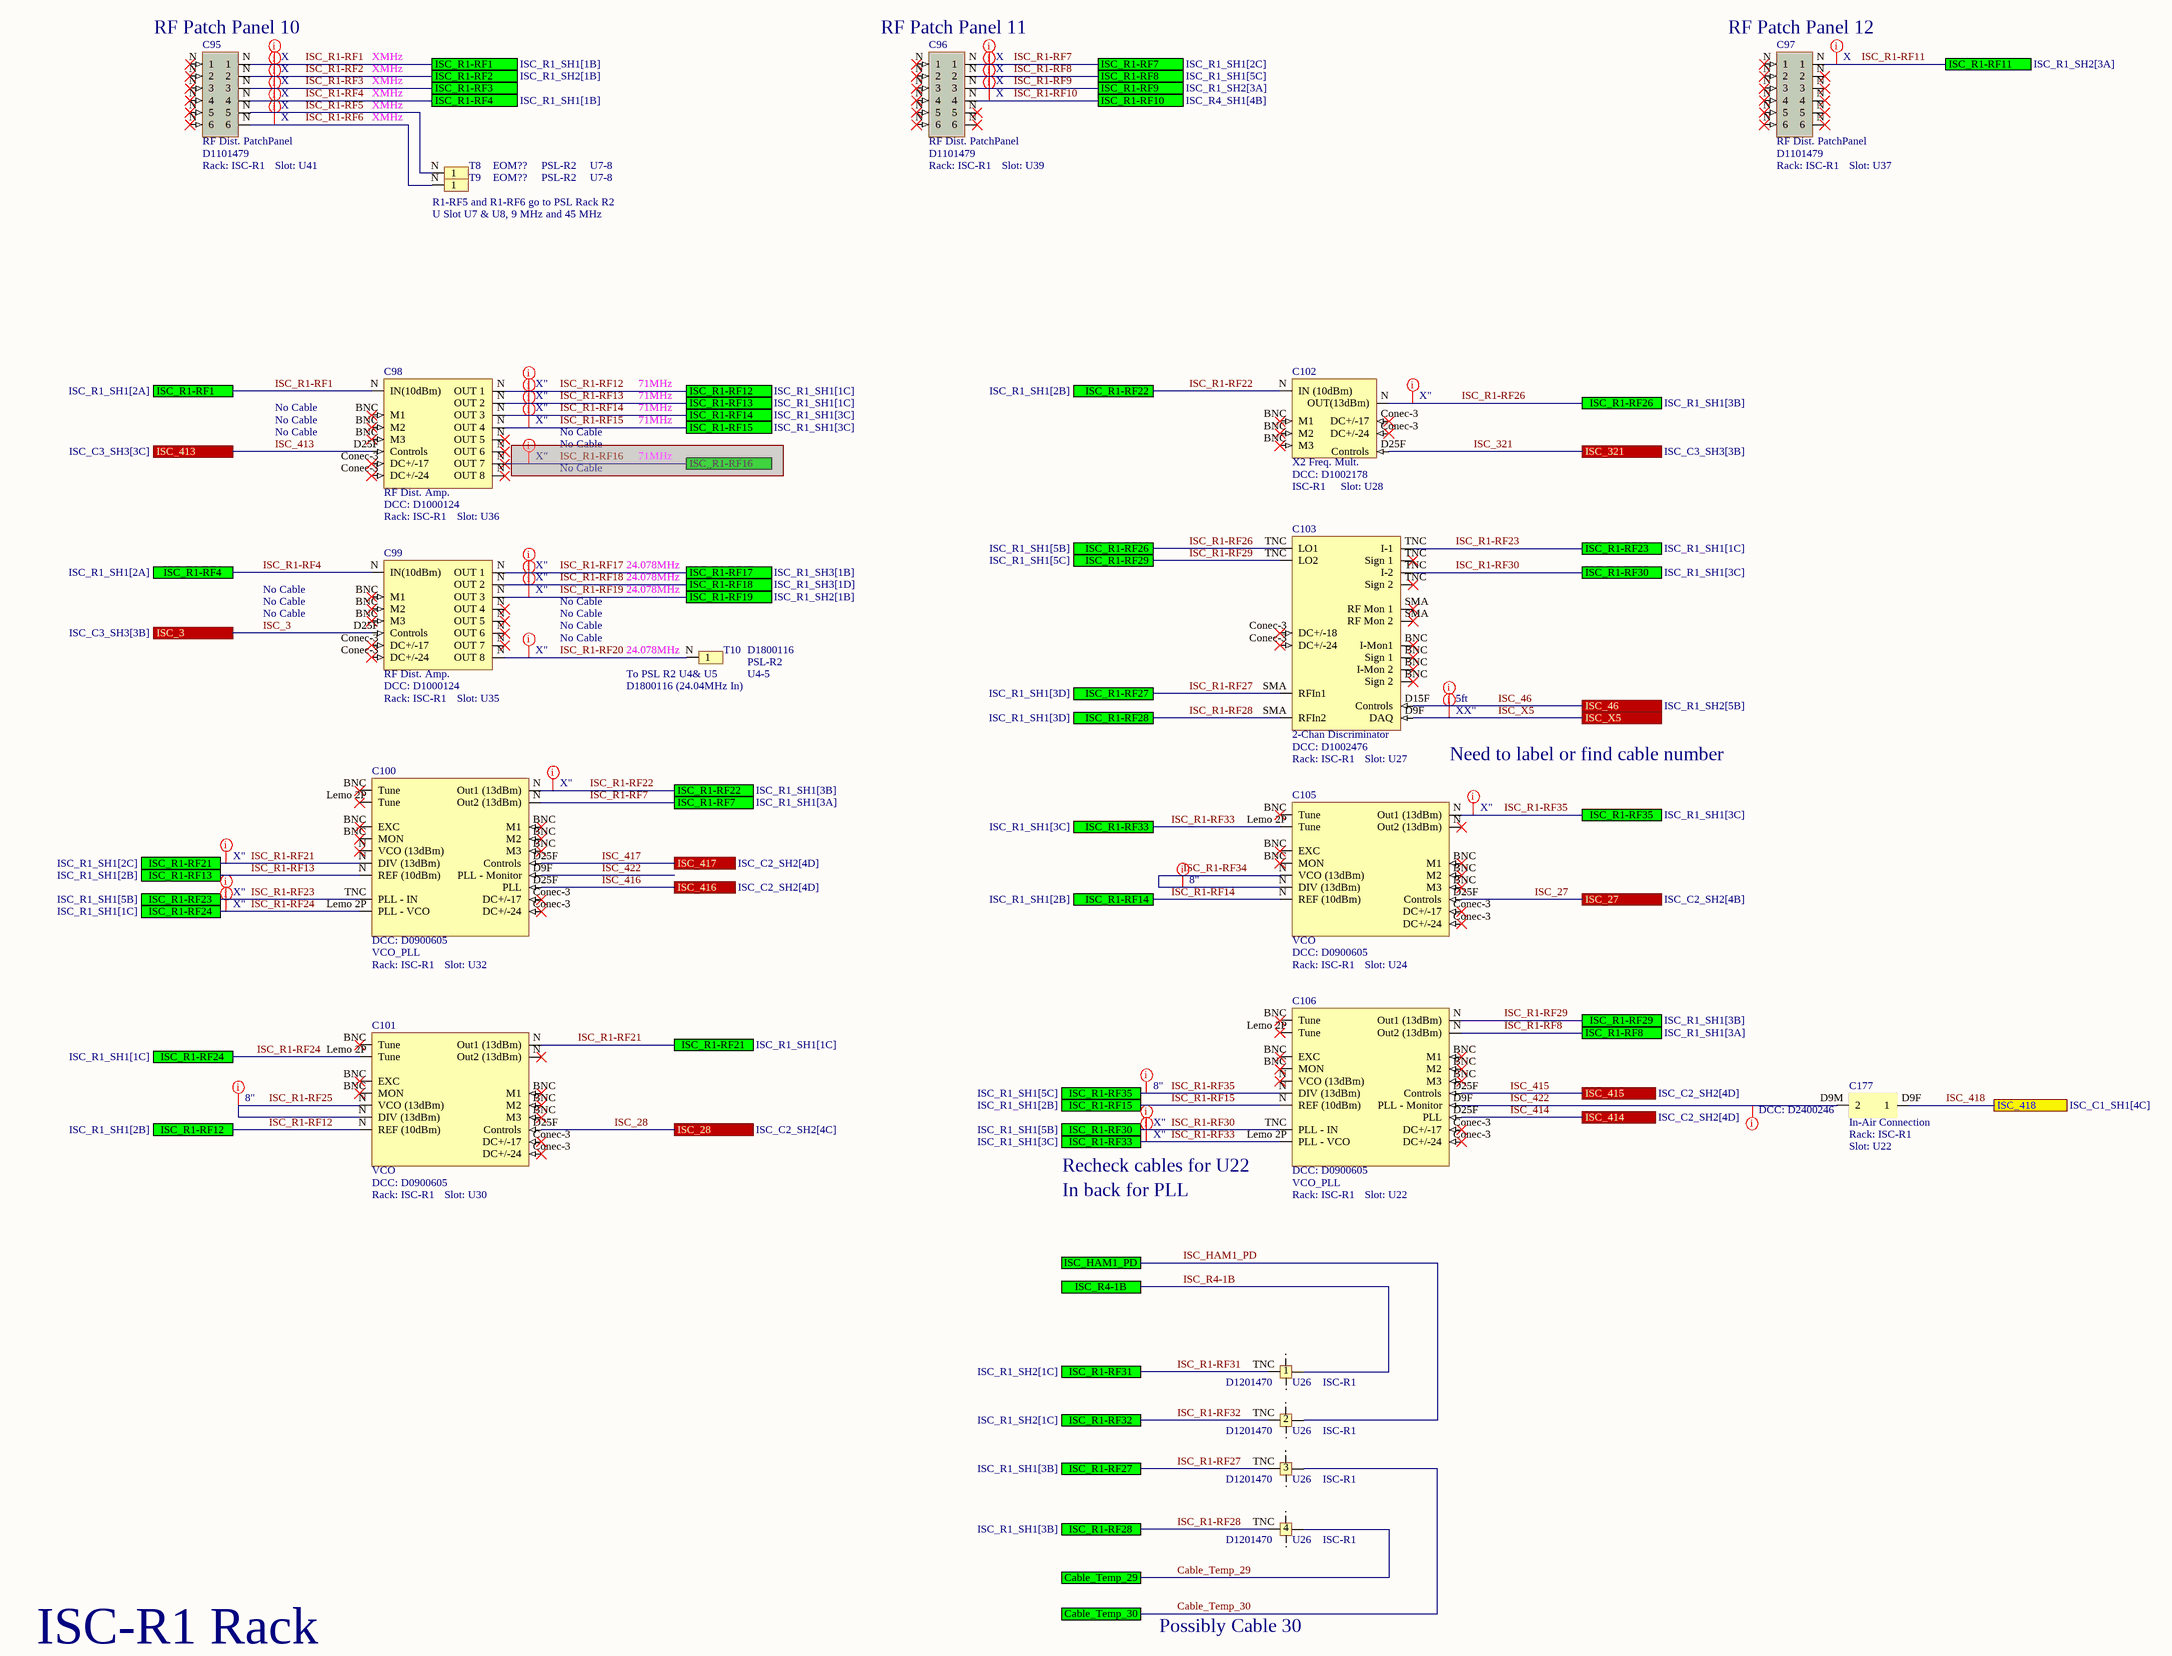
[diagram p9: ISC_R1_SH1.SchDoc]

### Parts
C95  RF Dist. PatchPanel  DCC: D1101479  Rack: ISC-R1  Slot: U41
C96  RF Dist. PatchPanel  DCC: D1101479  Rack: ISC-R1  Slot: U39
C97  RF Dist. PatchPanel  DCC: D1101479  Rack: ISC-R1  Slot: U37
C98  RF Dist. Amp.  DCC: D1000124  Rack: ISC-R1  Slot: U36
C99  RF Dist. Amp.  DCC: D1000124  Rack: ISC-R1  Slot: U35
C100  VCO_PLL  DCC: D0900605  Rack: ISC-R1  Slot: U32
C101  VCO  DCC: D0900605  Rack: ISC-R1  Slot: U30
C102  X2 Freq. Mult.  DCC: D1002178  Rack: ISC-R1  Slot: U28
C103  2-Chan Discriminator  DCC: D1002476  Rack: ISC-R1  Slot: U27
C104  DCC: D1201470  Rack: ISC-R1  Slot: U26  (hidden comment: Patch Panel TNC 1U)  (parts A,B,C,D of 4)
C105  VCO  DCC: D0900605  Rack: ISC-R1  Slot: U24
C106  VCO_PLL  DCC: D0900605  Rack: ISC-R1  Slot: U22
C177  In-Air Connection  Rack: ISC-R1  Slot: U22
T8  EOM??  Rack: PSL-R2  Slot: U7-8
T9  EOM??  Rack: PSL-R2  Slot: U7-8
T10  D1800116  Rack: PSL-R2  Slot: U4-5

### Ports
Cable_Temp_29, Cable_Temp_30, ISC_3 (see ISC_C3_SH3[3B]), ISC_27 (see ISC_C2_SH2[4B]), ISC_28 (see ISC_C2_SH2[4C]), ISC_46 (see ISC_R1_SH2[5B]), ISC_321 (see ISC_C3_SH3[3B]), ISC_413 (see ISC_C3_SH3[3C]), ISC_414 (see ISC_C2_SH2[4D]), ISC_415 (see ISC_C2_SH2[4D]), ISC_416 (see ISC_C2_SH2[4D]), ISC_417 (see ISC_C2_SH2[4D]), ISC_418 (see ISC_C1_SH1[4C]), ISC_HAM1_PD, ISC_R1-RF1 (see ISC_R1_SH1[1B]), ISC_R1-RF1 (see ISC_R1_SH1[2A]), ISC_R1-RF2 (see ISC_R1_SH2[1B]), ISC_R1-RF3, ISC_R1-RF4 (see ISC_R1_SH1[1B]), ISC_R1-RF4 (see ISC_R1_SH1[2A]), ISC_R1-RF7 (see ISC_R1_SH1[2C]), ISC_R1-RF7 (see ISC_R1_SH1[3A]), ISC_R1-RF8 (see ISC_R1_SH1[3A]), ISC_R1-RF8 (see ISC_R1_SH1[5C]), ISC_R1-RF9 (see ISC_R1_SH2[3A]), ISC_R1-RF10 (see ISC_R4_SH1[4B]), ISC_R1-RF11 (see ISC_R1_SH2[3A]), ISC_R1-RF12 (see ISC_R1_SH1[1C]), ISC_R1-RF12 (see ISC_R1_SH1[2B]), ISC_R1-RF13 (see ISC_R1_SH1[1C]), ISC_R1-RF13 (see ISC_R1_SH1[2B]), ISC_R1-RF14 (see ISC_R1_SH1[2B]), ISC_R1-RF14 (see ISC_R1_SH1[3C]), ISC_R1-RF15 (see ISC_R1_SH1[2B]), ISC_R1-RF15 (see ISC_R1_SH1[3C]), ISC_R1-RF16, ISC_R1-RF17 (see ISC_R1_SH3[1B]), ISC_R1-RF18 (see ISC_R1_SH3[1D]), ISC_R1-RF19 (see ISC_R1_SH2[1B]), ISC_R1-RF21 (see ISC_R1_SH1[1C]), ISC_R1-RF21 (see ISC_R1_SH1[2C]), ISC_R1-RF22 (see ISC_R1_SH1[2B]), ISC_R1-RF22 (see ISC_R1_SH1[3B]), ISC_R1-RF23 (see ISC_R1_SH1[1C]), ISC_R1-RF23 (see ISC_R1_SH1[5B]), ISC_R1-RF24 (see ISC_R1_SH1[1C]), ISC_R1-RF26 (see ISC_R1_SH1[3B]), ISC_R1-RF26 (see ISC_R1_SH1[5B]), ISC_R1-RF27 (see ISC_R1_SH1[3B]), ISC_R1-RF27 (see ISC_R1_SH1[3D]), ISC_R1-RF28 (see ISC_R1_SH1[3B]), ISC_R1-RF28 (see ISC_R1_SH1[3D]), ISC_R1-RF29 (see ISC_R1_SH1[3B]), ISC_R1-RF29 (see ISC_R1_SH1[5C]), ISC_R1-RF30 (see ISC_R1_SH1[3C]), ISC_R1-RF30 (see ISC_R1_SH1[5B]), ISC_R1-RF31 (see ISC_R1_SH2[1C]), ISC_R1-RF32 (see ISC_R1_SH2[1C]), ISC_R1-RF33 (see ISC_R1_SH1[3C]), ISC_R1-RF35 (see ISC_R1_SH1[3C]), ISC_R1-RF35 (see ISC_R1_SH1[5C]), ISC_R4-1B, ISC_X5

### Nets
Cable_Temp_29: C104.TNC ; port Cable_Temp_29
Cable_Temp_30: C104.TNC ; port Cable_Temp_30
ISC_3: C99.D25F(Controls) ; port ISC_3
ISC_27: C105.D25F(Controls) ; port ISC_27
ISC_28: C101.D25F(Controls) ; port ISC_28
ISC_46: C103.D15F(Controls) ; port ISC_46
ISC_321: C102.D25F(Controls) ; port ISC_321
ISC_413: C98.D25F(Controls) ; port ISC_413
ISC_414: C106.D25F(PLL) ; port ISC_414
ISC_415: C106.D25F(Controls) ; port ISC_415
ISC_416: C100.D25F(PLL) ; port ISC_416
ISC_417: C100.D25F(Controls) ; port ISC_417
ISC_418: C177.D9F(1) ; port ISC_418
ISC_422: C100.D9F(PLL_-_Monitor) C106.D9F(PLL_-_Monitor) C177.D9M(2)
ISC_HAM1_PD: C104.TNC ; port ISC_HAM1_PD
ISC_R1-RF1: C95.N(1) C98.N(IN(10dBm)) ; port ISC_R1-RF1
ISC_R1-RF2: C95.N(2) ; port ISC_R1-RF2
ISC_R1-RF3: C95.N(3) ; port ISC_R1-RF3
ISC_R1-RF4: C95.N(4) C99.N(IN(10dBm)) ; port ISC_R1-RF4
ISC_R1-RF5: C95.N(5) T8.N(1)
ISC_R1-RF6: C95.N(6) T9.N(1)
ISC_R1-RF7: C96.N(1) C100.N(Out2_(13dBm)) ; port ISC_R1-RF7
ISC_R1-RF8: C96.N(2) C106.N(Out2_(13dBm)) ; port ISC_R1-RF8
ISC_R1-RF9: C96.N(3) ; port ISC_R1-RF9
ISC_R1-RF10: C96.N(4) ; port ISC_R1-RF10
ISC_R1-RF11: C97.N(1) ; port ISC_R1-RF11
ISC_R1-RF12: C98.N(OUT_1) C101.N(REF_(10dBm)) ; port ISC_R1-RF12
ISC_R1-RF13: C98.N(OUT_2) C100.N(REF_(10dBm)) ; port ISC_R1-RF13
ISC_R1-RF14: C98.N(OUT_3) C105.N(REF_(10dBm)) ; port ISC_R1-RF14
ISC_R1-RF15: C98.N(OUT_4) C106.N(REF_(10dBm)) ; port ISC_R1-RF15
ISC_R1-RF17: C99.N(OUT_1) ; port ISC_R1-RF17
ISC_R1-RF18: C99.N(OUT_2) ; port ISC_R1-RF18
ISC_R1-RF19: C99.N(OUT_3) ; port ISC_R1-RF19
ISC_R1-RF20: C99.N(OUT_8) T10.N(1)
ISC_R1-RF21: C100.N(VCO_(13dBm)) C101.N(Out1_(13dBm)) ; port ISC_R1-RF21
ISC_R1-RF22: C100.N(Out1_(13dBm)) C102.N(IN_(10dBm)) ; port ISC_R1-RF22
ISC_R1-RF23: C100.TNC(PLL_-_IN) C103.TNC(I-1) ; port ISC_R1-RF23
ISC_R1-RF24: C100.Lemo_2P(Tune) C101.Lemo_2P(Tune) ; port ISC_R1-RF24
ISC_R1-RF25: C101.N(VCO_(13dBm))
ISC_R1-RF26: C102.N(OUT(13dBm)) C103.TNC(LO1) ; port ISC_R1-RF26
ISC_R1-RF27: C103.SMA(RF_Mon_1) C104.TNC ; port ISC_R1-RF27
ISC_R1-RF28: C103.SMA(RFIn2) C104.TNC ; port ISC_R1-RF28
ISC_R1-RF29: C103.TNC(LO2) C106.N(Out1_(13dBm)) ; port ISC_R1-RF29
ISC_R1-RF30: C103.TNC(I-2) C106.TNC(PLL_-_IN) ; port ISC_R1-RF30
ISC_R1-RF31: C104.TNC ; port ISC_R1-RF31
ISC_R1-RF32: C104.TNC ; port ISC_R1-RF32
ISC_R1-RF33: C105.Lemo_2P(Tune) C106.Lemo_2P(Tune) ; port ISC_R1-RF33
ISC_R1-RF34: C105.N(VCO_(13dBm))
ISC_R1-RF35: C105.N(Out1_(13dBm)) C106.N(VCO_(13dBm)) ; port ISC_R1-RF35
ISC_R4-1B: C104.TNC ; port ISC_R4-1B
ISC_X5: C103.D9F(DAQ) ; port ISC_X5

Not connected (* = marked no-connect by the designer): C98 BNC(M1)* Conec-3(DC+/-17)*; C99 BNC(M1)* Conec-3(DC+/-17)*; C100 BNC(Tune)* Conec-3(DC+/-17)*; C101 BNC(Tune)* Conec-3(DC+/-17)*; C102 BNC(M1)* Conec-3(DC+/-17)*; C103 BNC(I-Mon1)* Conec-3(DC+/-18)*; C105 BNC(Tune)* Conec-3(DC+/-17)*; C106 BNC(Tune)* Conec-3(DC+/-17)*

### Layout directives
Length: X": ISC_R1-RF12, ISC_R1-RF13, ISC_R1-RF14, ISC_R1-RF15, ISC_R1-RF17, ISC_R1-RF18, ISC_R1-RF19, ISC_R1-RF20, ISC_R1-RF21, ISC_R1-RF22, ISC_R1-RF23, ISC_R1-RF24, ISC_R1-RF26, ISC_R1-RF30, ISC_R1-RF33, ISC_R1-RF35
Length: X: ISC_R1-RF1, ISC_R1-RF2, ISC_R1-RF3, ISC_R1-RF4, ISC_R1-RF5, ISC_R1-RF6, ISC_R1-RF7, ISC_R1-RF8, ISC_R1-RF9, ISC_R1-RF10, ISC_R1-RF11
Length: 5ft: ISC_46
Length: XX": ISC_X5
Length: 8": ISC_R1-RF25, ISC_R1-RF34, ISC_R1-RF35
DCC: D2400246: ISC_422

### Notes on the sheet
- (near C95) RF Patch Panel 10
- (near C96) RF Patch Panel 11
- (near C97) RF Patch Panel 12
- XMHz
- (near T9) R1-RF5 and R1-RF6 go to PSL Rack R2
- U Slot U7 & U8, 9 MHz and 45 MHz
- 71MHz
- No Cable
- 24.078MHz
- (near T10) 24.078MHz
- (near T10) To PSL R2 U4& U5
- (near T10) D1800116 (24.04MHz In)
- Need to label or find cable number
- (near C106) Recheck cables for U22
- In back for PLL
- ISC-R1 Rack
- Possibly Cable 30

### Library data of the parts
C95-C97 = RF Dist. PatchPanel: Serial: Sxxxxxxx; System: ISC
C98 C99 = RF Distribution Amplifier: Serial: Sxxxxxxx; System: ISC
C100 C106 = VCO_PLL: Serial: Sxxxxxxx; System: ISC
C101 C105 = VCO: Serial: Sxxxxxxx; System: ISC
C102 = X2 Freq. Mult.: Serial: Sxxxxxxx; System: ISC
C103 = 2-Chan Discriminator: Serial: Sxxxxxxx; System: ISC
C104 = Patch Panel TNC 1U: Patch Panel (D1201470); Serial: Sxxxxxxx; System: ISC
C177 = InAirConnectionDB9: Serial: Sxxxxxxx; System: ISC
T8-T10 = Placeholder: IO Chassis; Serial: Sxxxxxxx; System: ISC; DCC: tbd

## Sheet ISC_R1_SH2.SchDoc: ISC System Wiring Diagram
size B; DrawnBy: Filiberto Clara; Engineer: Filiberto Clara; Organization: LIGO Laboratory; Address1: California Institute of Technology; Address2: Massachusetts Institute of Technology; DocumentNumber: D1900511; Revision: V11; SheetNumber: 11; SheetTotal: 39
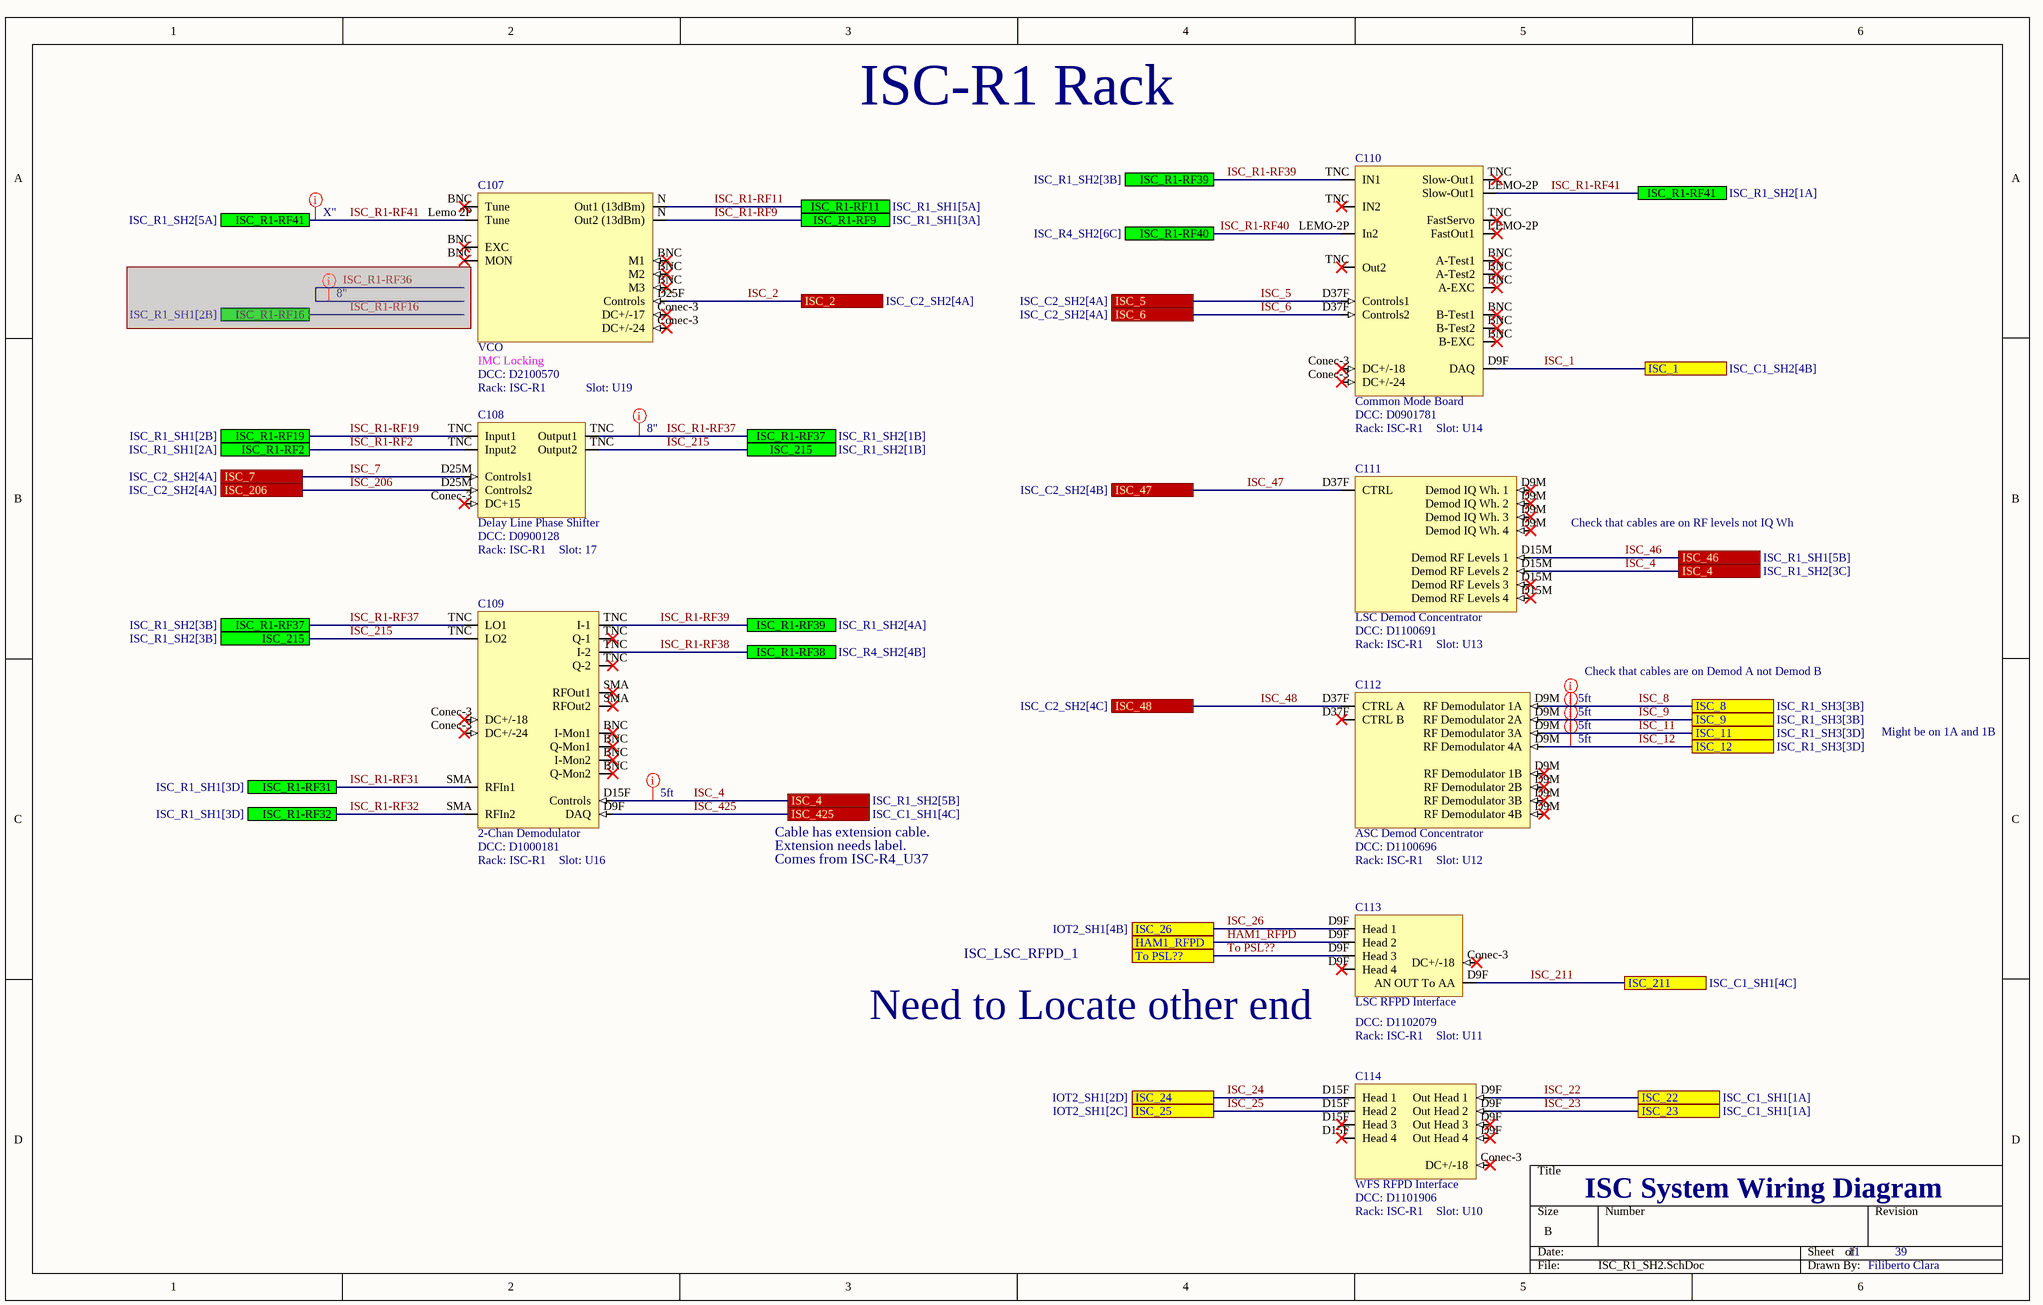
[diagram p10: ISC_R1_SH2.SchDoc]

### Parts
C107  VCO  DCC: D2100570  Rack: ISC-R1  Slot: U19
C108  Delay Line Phase Shifter  DCC: D0900128  Rack: ISC-R1  Slot: 17
C109  2-Chan Demodulator  DCC: D1000181  Rack: ISC-R1  Slot: U16
C110  Common Mode Board  DCC: D0901781  Rack: ISC-R1  Slot: U14
C111  LSC Demod Concentrator  DCC: D1100691  Rack: ISC-R1  Slot: U13
C112  ASC Demod Concentrator  DCC: D1100696  Rack: ISC-R1  Slot: U12
C113  LSC RFPD Interface  DCC: D1102079  Rack: ISC-R1  Slot: U11
C114  WFS RFPD Interface  DCC: D1101906  Rack: ISC-R1  Slot: U10

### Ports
HAM1_RFPD, ISC_1 (see ISC_C1_SH2[4B]), ISC_2 (see ISC_C2_SH2[4A]), ISC_4 (see ISC_R1_SH2[3C]), ISC_4 (see ISC_R1_SH2[5B]), ISC_5 (see ISC_C2_SH2[4A]), ISC_6 (see ISC_C2_SH2[4A]), ISC_7 (see ISC_C2_SH2[4A]), ISC_8 (see ISC_R1_SH3[3B]), ISC_9 (see ISC_R1_SH3[3B]), ISC_11 (see ISC_R1_SH3[3D]), ISC_12 (see ISC_R1_SH3[3D]), ISC_22 (see ISC_C1_SH1[1A]), ISC_23 (see ISC_C1_SH1[1A]), ISC_24 (see IOT2_SH1[2D]), ISC_25 (see IOT2_SH1[2C]), ISC_26 (see IOT2_SH1[4B]), ISC_46 (see ISC_R1_SH1[5B]), ISC_47 (see ISC_C2_SH2[4B]), ISC_48 (see ISC_C2_SH2[4C]), ISC_206 (see ISC_C2_SH2[4A]), ISC_211 (see ISC_C1_SH1[4C]), ISC_215 (see ISC_R1_SH2[1B]), ISC_215 (see ISC_R1_SH2[3B]), ISC_425 (see ISC_C1_SH1[4C]), ISC_R1-RF2 (see ISC_R1_SH1[2A]), ISC_R1-RF9 (see ISC_R1_SH1[3A]), ISC_R1-RF11 (see ISC_R1_SH1[5A]), ISC_R1-RF16 (see ISC_R1_SH1[2B]), ISC_R1-RF19 (see ISC_R1_SH1[2B]), ISC_R1-RF31 (see ISC_R1_SH1[3D]), ISC_R1-RF32 (see ISC_R1_SH1[3D]), ISC_R1-RF37 (see ISC_R1_SH2[1B]), ISC_R1-RF37 (see ISC_R1_SH2[3B]), ISC_R1-RF38 (see ISC_R4_SH2[4B]), ISC_R1-RF39 (see ISC_R1_SH2[3B]), ISC_R1-RF39 (see ISC_R1_SH2[4A]), ISC_R1-RF40 (see ISC_R4_SH2[6C]), ISC_R1-RF41 (see ISC_R1_SH2[1A]), ISC_R1-RF41 (see ISC_R1_SH2[5A]), To PSL??

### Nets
HAM1_RFPD: C113.D9F(Head_2) ; port HAM1_RFPD
ISC_1: C110.D9F(DAQ) ; port ISC_1
ISC_2: C107.D25F(Controls) ; port ISC_2
ISC_4: C109.D15F(Controls) C111.D15M(Demod_RF_Levels_2) ; port ISC_4
ISC_5: C110.D37F(Controls1) ; port ISC_5
ISC_6: C110.D37F(Controls2) ; port ISC_6
ISC_7: C108.D25M(Controls1) ; port ISC_7
ISC_8: C112.D9M(RF_Demodulator_1A) ; port ISC_8
ISC_9: C112.D9M(RF_Demodulator_2A) ; port ISC_9
ISC_11: C112.D9M(RF_Demodulator_3A) ; port ISC_11
ISC_12: C112.D9M(RF_Demodulator_4A) ; port ISC_12
ISC_22: C114.D9F(Out_Head_1) ; port ISC_22
ISC_23: C114.D9F(Out_Head_2) ; port ISC_23
ISC_24: C114.D15F(Head_1) ; port ISC_24
ISC_25: C114.D15F(Head_2) ; port ISC_25
ISC_26: C113.D9F(Head_1) ; port ISC_26
ISC_46: C111.D15M(Demod_RF_Levels_1) ; port ISC_46
ISC_47: C111.D37F(CTRL) ; port ISC_47
ISC_48: C112.D37F(CTRL_A) ; port ISC_48
ISC_206: C108.D25M(Controls2) ; port ISC_206
ISC_211: C113.D9F(AN_OUT_To_AA) ; port ISC_211
ISC_215: C108.TNC(Output2) C109.TNC(LO2) ; port ISC_215
ISC_425: C109.D9F(DAQ) ; port ISC_425
ISC_R1-RF2: C108.TNC(Input2) ; port ISC_R1-RF2
ISC_R1-RF9: C107.N(Out2_(13dBm)) ; port ISC_R1-RF9
ISC_R1-RF11: C107.N(Out1_(13dBm)) ; port ISC_R1-RF11
ISC_R1-RF19: C108.TNC(Input1) ; port ISC_R1-RF19
ISC_R1-RF31: C109.SMA(RFOut1) ; port ISC_R1-RF31
ISC_R1-RF32: C109.SMA(RFIn2) ; port ISC_R1-RF32
ISC_R1-RF37: C108.TNC(Output1) C109.TNC(LO1) ; port ISC_R1-RF37
ISC_R1-RF38: C109.TNC(I-2) ; port ISC_R1-RF38
ISC_R1-RF39: C109.TNC(I-1) C110.TNC(IN1) ; port ISC_R1-RF39
ISC_R1-RF40: C110.LEMO-2P(In2) ; port ISC_R1-RF40
ISC_R1-RF41: C107.Lemo_2P(Tune) C110.LEMO-2P(Slow-Out1) ; port ISC_R1-RF41
To PSL??: C113.D9F(Head_3) ; port To PSL??

Not connected (* = marked no-connect by the designer): C107 BNC(Tune)* Conec-3(DC+/-17)*; C108 Conec-3(DC+15)*; C109 BNC(I-Mon1)* Conec-3(DC+/-18)*; C110 BNC(A-Test1)* Conec-3(DC+/-18)*; C111 D9M(Demod_IQ_Wh._1)*; C113 Conec-3(DC+/-18)*; C114 Conec-3(DC+/-18)*

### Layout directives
Length: 5ft: ISC_4, ISC_8, ISC_9, ISC_11, ISC_12
Length: 8": (no net found under the mark), ISC_R1-RF37
Length: X": ISC_R1-RF41

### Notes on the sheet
- ISC-R1 Rack
- (near C107) IMC Locking
- Check that cables are on RF levels not IQ Wh
- Check that cables are on Demod A not Demod B
- Might be on 1A and 1B
- Cable has extension cable.
- Extension needs label.
- Comes from ISC-R4_U37
- ISC_LSC_RFPD_1
- (near C113) Need to Locate other end

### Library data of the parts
C107 = VCONew: New VCO; Serial: Sxxxxxxx; System: ISC
C108 = DelayLinePhaseShifter: Serial: Sxxxxxxx; System: ISC
C109 = 2-Chan Demod: Serial: Sxxxxxxx; System: ISC
C110 = CommonModeBoard: Serial: Sxxxxxxx; System: ISC
C111 = LSC Demod Concentrator: Serial: Sxxxxxxx; System: ISC
C112 = ASC Demod Concentrator: Serial: Sxxxxxxx; System: ISC
C113 = LSC RFPD Interface: Serial: Sxxxxxxx; System: ISC
C114 = WFS RFPD Interface: Serial: Sxxxxxxx; System: ISC

## Sheet ISC_R1_SH3.SchDoc: ISC System Wiring Diagram
size B; DrawnBy: Filiberto Clara; Engineer: Filiberto Clara; Organization: LIGO Laboratory; Address1: California Institute of Technology; Address2: Massachusetts Institute of Technology; DocumentNumber: D1900511; Revision: V11; SheetNumber: 12; SheetTotal: 39
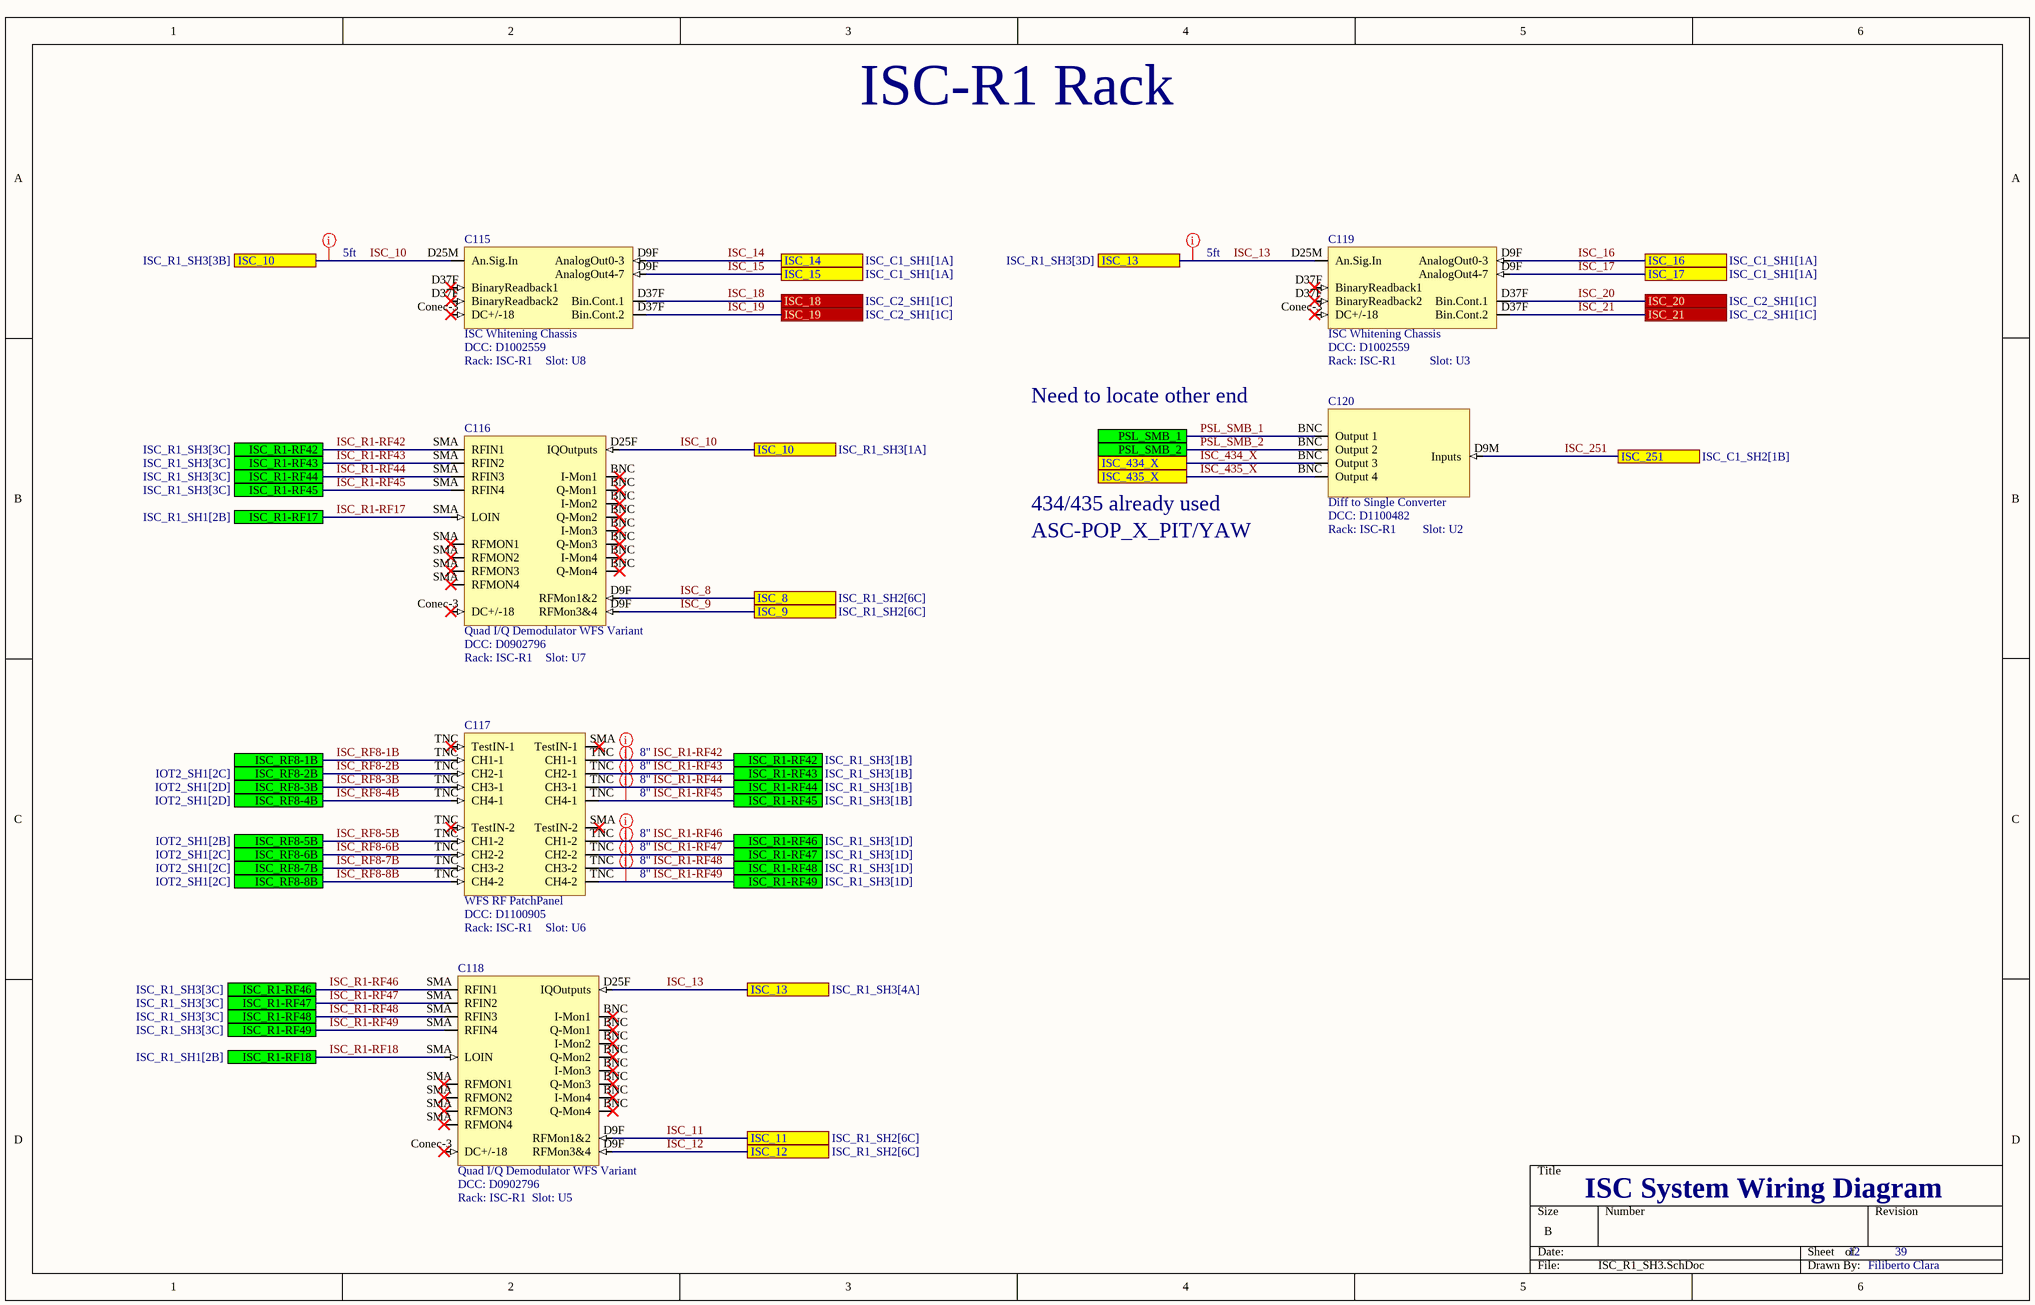
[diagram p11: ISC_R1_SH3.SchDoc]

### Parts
C115  ISC Whitening Chassis  DCC: D1002559  Rack: ISC-R1  Slot: U8
C116  Quad I/Q Demodulator WFS Variant  DCC: D0902796  Rack: ISC-R1  Slot: U7
C117  WFS RF PatchPanel  DCC: D1100905  Rack: ISC-R1  Slot: U6
C118  Quad I/Q Demodulator WFS Variant  DCC: D0902796  Rack: ISC-R1  Slot: U5
C119  ISC Whitening Chassis  DCC: D1002559  Rack: ISC-R1  Slot: U3
C120  Diff to Single Converter  DCC: D1100482  Rack: ISC-R1  Slot: U2

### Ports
ISC_8 (see ISC_R1_SH2[6C]), ISC_9 (see ISC_R1_SH2[6C]), ISC_10 (see ISC_R1_SH3[1A]), ISC_10 (see ISC_R1_SH3[3B]), ISC_11 (see ISC_R1_SH2[6C]), ISC_12 (see ISC_R1_SH2[6C]), ISC_13 (see ISC_R1_SH3[3D]), ISC_13 (see ISC_R1_SH3[4A]), ISC_14 (see ISC_C1_SH1[1A]), ISC_15 (see ISC_C1_SH1[1A]), ISC_16 (see ISC_C1_SH1[1A]), ISC_17 (see ISC_C1_SH1[1A]), ISC_18 (see ISC_C2_SH1[1C]), ISC_19 (see ISC_C2_SH1[1C]), ISC_20 (see ISC_C2_SH1[1C]), ISC_21 (see ISC_C2_SH1[1C]), ISC_251 (see ISC_C1_SH2[1B]), ISC_434_X, ISC_435_X, ISC_R1-RF17 (see ISC_R1_SH1[2B]), ISC_R1-RF18 (see ISC_R1_SH1[2B]), ISC_R1-RF42 (see ISC_R1_SH3[1B]), ISC_R1-RF42 (see ISC_R1_SH3[3C]), ISC_R1-RF43 (see ISC_R1_SH3[1B]), ISC_R1-RF43 (see ISC_R1_SH3[3C]), ISC_R1-RF44 (see ISC_R1_SH3[1B]), ISC_R1-RF44 (see ISC_R1_SH3[3C]), ISC_R1-RF45 (see ISC_R1_SH3[1B]), ISC_R1-RF45 (see ISC_R1_SH3[3C]), ISC_R1-RF46 (see ISC_R1_SH3[1D]), ISC_R1-RF46 (see ISC_R1_SH3[3C]), ISC_R1-RF47 (see ISC_R1_SH3[1D]), ISC_R1-RF47 (see ISC_R1_SH3[3C]), ISC_R1-RF48 (see ISC_R1_SH3[1D]), ISC_R1-RF48 (see ISC_R1_SH3[3C]), ISC_R1-RF49 (see ISC_R1_SH3[1D]), ISC_R1-RF49 (see ISC_R1_SH3[3C]), ISC_RF8-1B, ISC_RF8-2B (see IOT2_SH1[2C]), ISC_RF8-3B (see IOT2_SH1[2D]), ISC_RF8-4B (see IOT2_SH1[2D]), ISC_RF8-5B (see IOT2_SH1[2B]), ISC_RF8-6B (see IOT2_SH1[2C]), ISC_RF8-7B (see IOT2_SH1[2C]), ISC_RF8-8B (see IOT2_SH1[2C]), PSL_SMB_1, PSL_SMB_2

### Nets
ISC_8: C116.D9F(RFMon1&2) ; port ISC_8
ISC_9: C116.D9F(RFMon3&4) ; port ISC_9
ISC_10: C115.D25M(An.Sig.In) C116.D25F(IQOutputs) ; port ISC_10
ISC_11: C118.D9F(RFMon1&2) ; port ISC_11
ISC_12: C118.D9F(RFMon3&4) ; port ISC_12
ISC_13: C118.D25F(IQOutputs) C119.D25M(An.Sig.In) ; port ISC_13
ISC_14: C115.D9F(AnalogOut0-3) ; port ISC_14
ISC_15: C115.D9F(AnalogOut4-7) ; port ISC_15
ISC_16: C119.D9F(AnalogOut0-3) ; port ISC_16
ISC_17: C119.D9F(AnalogOut4-7) ; port ISC_17
ISC_18: C115.D37F(BinaryReadback1) ; port ISC_18
ISC_19: C115.D37F(Bin.Cont.2) ; port ISC_19
ISC_20: C119.D37F(BinaryReadback1) ; port ISC_20
ISC_21: C119.D37F(Bin.Cont.2) ; port ISC_21
ISC_251: C120.D9M(Inputs) ; port ISC_251
ISC_434_X: C120.BNC(Output_3) ; port ISC_434_X
ISC_435_X: C120.BNC(Output_4) ; port ISC_435_X
ISC_R1-RF17: C116.SMA(LOIN) ; port ISC_R1-RF17
ISC_R1-RF18: C118.SMA(LOIN) ; port ISC_R1-RF18
ISC_R1-RF42: C116.SMA(RFIN1) C117.TNC(CH1-1) ; port ISC_R1-RF42
ISC_R1-RF43: C116.SMA(RFIN2) C117.TNC(CH2-1) ; port ISC_R1-RF43
ISC_R1-RF44: C116.SMA(RFIN3) C117.TNC(CH3-1) ; port ISC_R1-RF44
ISC_R1-RF45: C116.SMA(RFIN4) C117.TNC(CH4-1) ; port ISC_R1-RF45
ISC_R1-RF46: C117.TNC(CH1-2) C118.SMA(RFIN1) ; port ISC_R1-RF46
ISC_R1-RF47: C117.TNC(CH2-2) C118.SMA(RFIN2) ; port ISC_R1-RF47
ISC_R1-RF48: C117.TNC(CH3-2) C118.SMA(RFIN3) ; port ISC_R1-RF48
ISC_R1-RF49: C117.TNC(CH4-2) C118.SMA(RFIN4) ; port ISC_R1-RF49
ISC_RF8-1B: C117.TNC(TestIN-1) ; port ISC_RF8-1B
ISC_RF8-2B: C117.TNC(CH2-1) ; port ISC_RF8-2B
ISC_RF8-3B: C117.TNC(CH3-1) ; port ISC_RF8-3B
ISC_RF8-4B: C117.TNC(CH4-1) ; port ISC_RF8-4B
ISC_RF8-5B: C117.TNC(CH1-2) ; port ISC_RF8-5B
ISC_RF8-6B: C117.TNC(CH2-2) ; port ISC_RF8-6B
ISC_RF8-7B: C117.TNC(CH3-2) ; port ISC_RF8-7B
ISC_RF8-8B: C117.TNC(CH4-2) ; port ISC_RF8-8B
PSL_SMB_1: C120.BNC(Output_1) ; port PSL_SMB_1
PSL_SMB_2: C120.BNC(Output_2) ; port PSL_SMB_2

Not connected (* = marked no-connect by the designer): C115 Conec-3(DC+/-18)*; C116 BNC(I-Mon1)* Conec-3(DC+/-18)*; C117 SMA(TestIN-1)*; C118 BNC(I-Mon1)* Conec-3(DC+/-18)*; C119 Conec-3(DC+/-18)*

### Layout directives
Length: 5ft: ISC_10, ISC_13
Length: 8": ISC_R1-RF42, ISC_R1-RF43, ISC_R1-RF44, ISC_R1-RF45, ISC_R1-RF46, ISC_R1-RF47, ISC_R1-RF48, ISC_R1-RF49

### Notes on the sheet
- ISC-R1 Rack
- (near C120) Need to locate other end
- 434/435 already used
- ASC-POP_X_PIT/YAW

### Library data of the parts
C115 C119 = ISC Whitening: Serial: Sxxxxxxx
C116 C118 = QuadIQdemod_WFS: Serial: Sxxxxxxx; System: ISC
C117 = WFS RFPD PatchPanel: Serial: Sxxxxxxx; System: ISC
C120 = Diff to Single Converter: Serial: Sxxxxxxx; System: ISC

## Sheet ISC_R2_SH1.SchDoc: ISC System Wiring Diagram
size C; DrawnBy: Filiberto Clara; Engineer: Filiberto Clara; Organization: LIGO Laboratory; Address1: California Institute of Technology; Address2: Massachusetts Institute of Technology; DocumentNumber: D1900511; Revision: V11; SheetNumber: 13; SheetTotal: 39
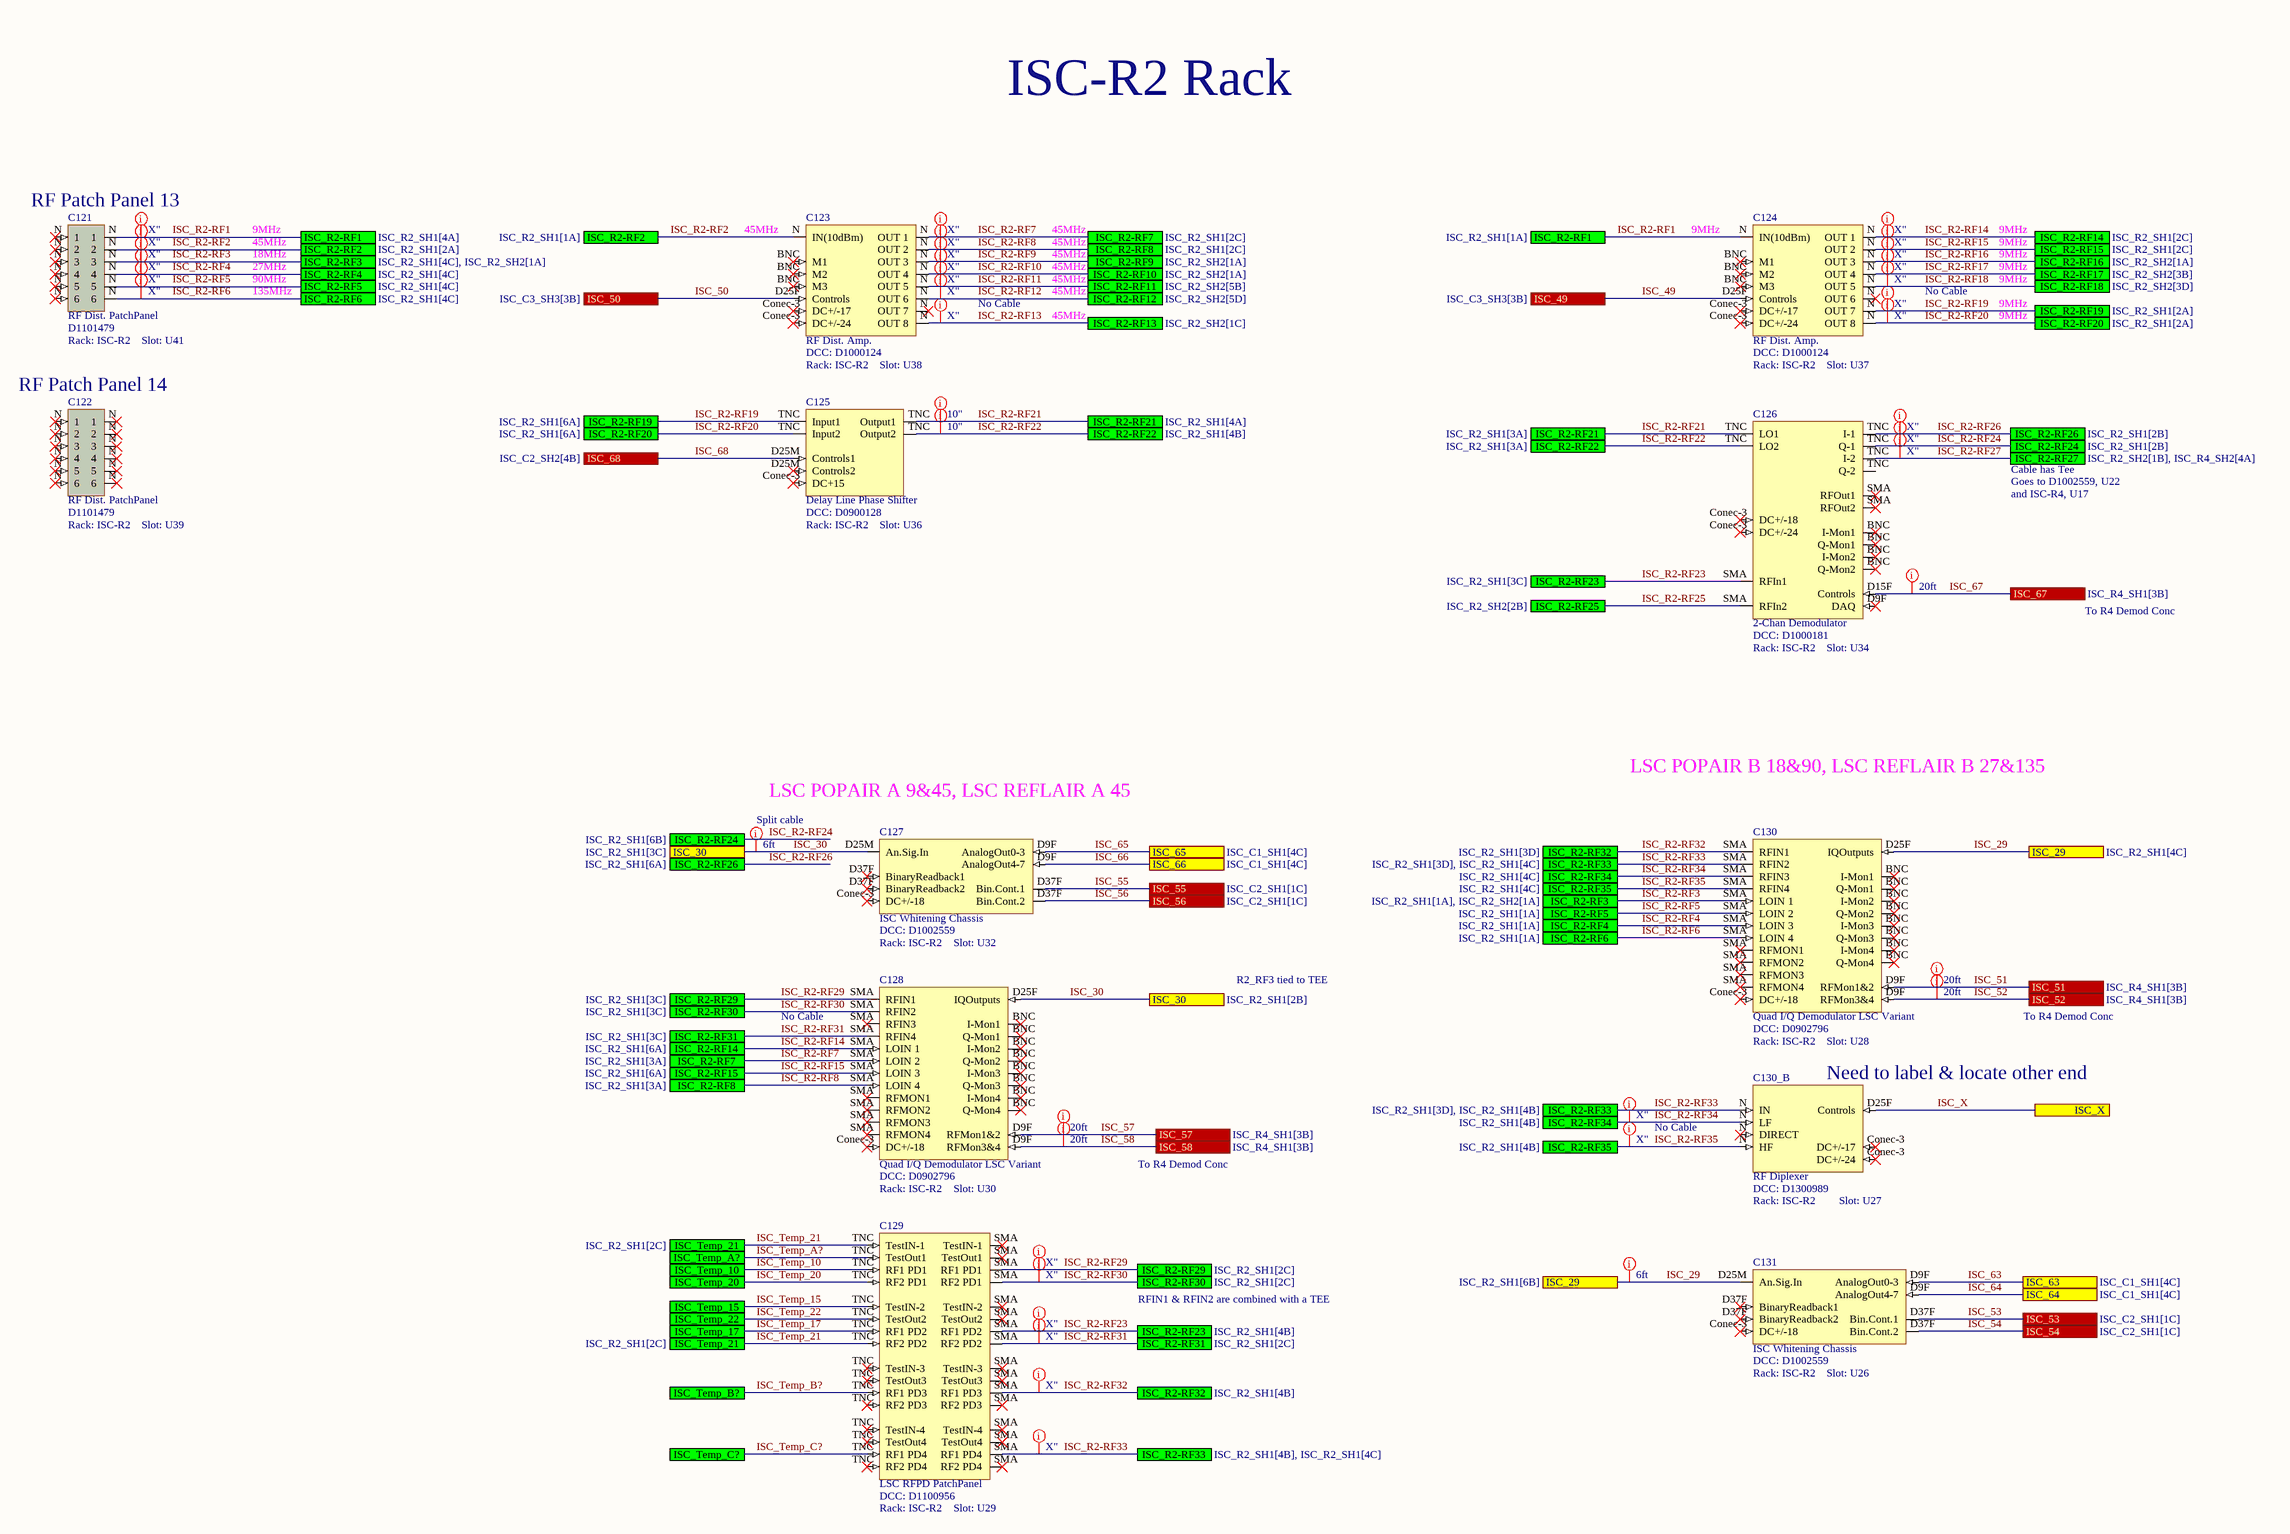
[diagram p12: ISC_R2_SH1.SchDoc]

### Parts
C121  RF Dist. PatchPanel  DCC: D1101479  Rack: ISC-R2  Slot: U41
C122  RF Dist. PatchPanel  DCC: D1101479  Rack: ISC-R2  Slot: U39
C123  RF Dist. Amp.  DCC: D1000124  Rack: ISC-R2  Slot: U38
C124  RF Dist. Amp.  DCC: D1000124  Rack: ISC-R2  Slot: U37
C125  Delay Line Phase Shifter  DCC: D0900128  Rack: ISC-R2  Slot: U36
C126  2-Chan Demodulator  DCC: D1000181  Rack: ISC-R2  Slot: U34
C127  ISC Whitening Chassis  DCC: D1002559  Rack: ISC-R2  Slot: U32
C128  Quad I/Q Demodulator LSC Variant  DCC: D0902796  Rack: ISC-R2  Slot: U30
C129  LSC RFPD PatchPanel  DCC: D1100956  Rack: ISC-R2  Slot: U29
C130  Quad I/Q Demodulator LSC Variant  DCC: D0902796  Rack: ISC-R2  Slot: U28
C130_B  RF Diplexer  DCC: D1300989  Rack: ISC-R2  Slot: U27
C131  ISC Whitening Chassis  DCC: D1002559  Rack: ISC-R2  Slot: U26

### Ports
ISC_29 (see ISC_R2_SH1[4C]), ISC_29 (see ISC_R2_SH1[6B]), ISC_30 (see ISC_R2_SH1[2B]), ISC_30 (see ISC_R2_SH1[3C]), ISC_49 (see ISC_C3_SH3[3B]), ISC_50 (see ISC_C3_SH3[3B]), ISC_51 (see ISC_R4_SH1[3B]), ISC_52 (see ISC_R4_SH1[3B]), ISC_53 (see ISC_C2_SH1[1C]), ISC_54 (see ISC_C2_SH1[1C]), ISC_55 (see ISC_C2_SH1[1C]), ISC_56 (see ISC_C2_SH1[1C]), ISC_57 (see ISC_R4_SH1[3B]), ISC_58 (see ISC_R4_SH1[3B]), ISC_63 (see ISC_C1_SH1[4C]), ISC_64 (see ISC_C1_SH1[4C]), ISC_65 (see ISC_C1_SH1[4C]), ISC_66 (see ISC_C1_SH1[4C]), ISC_67 (see ISC_R4_SH1[3B]), ISC_68 (see ISC_C2_SH2[4B]), ISC_R2-RF1 (see ISC_R2_SH1[1A]), ISC_R2-RF1 (see ISC_R2_SH1[4A]), ISC_R2-RF2 (see ISC_R2_SH1[1A]), ISC_R2-RF2 (see ISC_R2_SH1[2A]), ISC_R2-RF3 (see ISC_R2_SH1[1A], ISC_R2_SH2[1A]), ISC_R2-RF3 (see ISC_R2_SH1[4C], ISC_R2_SH2[1A]), ISC_R2-RF4 (see ISC_R2_SH1[1A]), ISC_R2-RF4 (see ISC_R2_SH1[4C]), ISC_R2-RF5 (see ISC_R2_SH1[1A]), ISC_R2-RF5 (see ISC_R2_SH1[4C]), ISC_R2-RF6 (see ISC_R2_SH1[1A]), ISC_R2-RF6 (see ISC_R2_SH1[4C]), ISC_R2-RF7 (see ISC_R2_SH1[2C]), ISC_R2-RF7 (see ISC_R2_SH1[3A]), ISC_R2-RF8 (see ISC_R2_SH1[2C]), ISC_R2-RF8 (see ISC_R2_SH1[3A]), ISC_R2-RF9 (see ISC_R2_SH2[1A]), ISC_R2-RF10 (see ISC_R2_SH2[1A]), ISC_R2-RF11 (see ISC_R2_SH2[5B]), ISC_R2-RF12 (see ISC_R2_SH2[5D]), ISC_R2-RF13 (see ISC_R2_SH2[1C]), ISC_R2-RF14 (see ISC_R2_SH1[2C]), ISC_R2-RF14 (see ISC_R2_SH1[6A]), ISC_R2-RF15 (see ISC_R2_SH1[2C]), ISC_R2-RF15 (see ISC_R2_SH1[6A]), ISC_R2-RF16 (see ISC_R2_SH2[1A]), ISC_R2-RF17 (see ISC_R2_SH2[3B]), ISC_R2-RF18 (see ISC_R2_SH2[3D]), ISC_R2-RF19 (see ISC_R2_SH1[2A]), ISC_R2-RF19 (see ISC_R2_SH1[6A]), ISC_R2-RF20 (see ISC_R2_SH1[2A]), ISC_R2-RF20 (see ISC_R2_SH1[6A]), ISC_R2-RF21 (see ISC_R2_SH1[3A]), ISC_R2-RF21 (see ISC_R2_SH1[4A]), ISC_R2-RF22 (see ISC_R2_SH1[3A]), ISC_R2-RF22 (see ISC_R2_SH1[4B]), ISC_R2-RF23 (see ISC_R2_SH1[3C]), ISC_R2-RF23 (see ISC_R2_SH1[4B]), ISC_R2-RF24 (see ISC_R2_SH1[2B]), ISC_R2-RF24 (see ISC_R2_SH1[6B]), ISC_R2-RF25 (see ISC_R2_SH2[2B]), ISC_R2-RF26 (see ISC_R2_SH1[2B]), ISC_R2-RF26 (see ISC_R2_SH1[6A]), ISC_R2-RF27 (see ISC_R2_SH2[1B], ISC_R4_SH2[4A]), ISC_R2-RF29 (see ISC_R2_SH1[2C]), ISC_R2-RF29 (see ISC_R2_SH1[3C]), ISC_R2-RF30 (see ISC_R2_SH1[2C]), ISC_R2-RF30 (see ISC_R2_SH1[3C]), ISC_R2-RF31 (see ISC_R2_SH1[2C]), ISC_R2-RF31 (see ISC_R2_SH1[3C]), ISC_R2-RF32 (see ISC_R2_SH1[3D]), ISC_R2-RF32 (see ISC_R2_SH1[4B]), ISC_R2-RF33 (see ISC_R2_SH1[3D], ISC_R2_SH1[4B]), ISC_R2-RF33 (see ISC_R2_SH1[3D], ISC_R2_SH1[4C]), ISC_R2-RF33 (see ISC_R2_SH1[4B], ISC_R2_SH1[4C]), ISC_R2-RF34 (see ISC_R2_SH1[4B]), ISC_R2-RF34 (see ISC_R2_SH1[4C]), ISC_R2-RF35 (see ISC_R2_SH1[4B]), ISC_R2-RF35 (see ISC_R2_SH1[4C]), ISC_Temp_10, ISC_Temp_15, ISC_Temp_17, ISC_Temp_20, ISC_Temp_21 (see ISC_R2_SH1[2C]), ISC_Temp_22, ISC_Temp_A?, ISC_Temp_B?, ISC_Temp_C?, ISC_X

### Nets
ISC_29: C130.D25F(IQOutputs) C131.D25M(An.Sig.In) ; port ISC_29
ISC_30: C127.D25M(An.Sig.In) C128.D25F(IQOutputs) ; port ISC_30
ISC_49: C124.D25F(Controls) ; port ISC_49
ISC_50: C123.D25F(Controls) ; port ISC_50
ISC_51: C130.D9F(RFMon1&2) ; port ISC_51
ISC_52: C130.D9F(RFMon3&4) ; port ISC_52
ISC_53: C131.D37F(BinaryReadback1) ; port ISC_53
ISC_54: C131.D37F(Bin.Cont.2) ; port ISC_54
ISC_55: C127.D37F(BinaryReadback1) ; port ISC_55
ISC_56: C127.D37F(Bin.Cont.2) ; port ISC_56
ISC_57: C128.D9F(RFMon1&2) ; port ISC_57
ISC_58: C128.D9F(RFMon3&4) ; port ISC_58
ISC_63: C131.D9F(AnalogOut0-3) ; port ISC_63
ISC_64: C131.D9F(AnalogOut4-7) ; port ISC_64
ISC_65: C127.D9F(AnalogOut0-3) ; port ISC_65
ISC_66: C127.D9F(AnalogOut4-7) ; port ISC_66
ISC_67: C126.D15F(Controls) ; port ISC_67
ISC_68: C125.D25M(Controls1) ; port ISC_68
ISC_R2-RF1: C121.N(1) C124.N(IN(10dBm)) ; port ISC_R2-RF1
ISC_R2-RF2: C121.N(2) C123.N(IN(10dBm)) ; port ISC_R2-RF2
ISC_R2-RF3: C121.N(3) C130.SMA(LOIN_1) ; port ISC_R2-RF3
ISC_R2-RF4: C121.N(4) C130.SMA(LOIN_3) ; port ISC_R2-RF4
ISC_R2-RF5: C121.N(5) C130.SMA(LOIN_2) ; port ISC_R2-RF5
ISC_R2-RF6: C121.N(6) C130.SMA(LOIN_4) ; port ISC_R2-RF6
ISC_R2-RF7: C123.N(OUT_1) C128.SMA(LOIN_2) ; port ISC_R2-RF7
ISC_R2-RF8: C123.N(OUT_2) C128.SMA(LOIN_4) ; port ISC_R2-RF8
ISC_R2-RF9: C123.N(OUT_3) ; port ISC_R2-RF9
ISC_R2-RF10: C123.N(OUT_4) ; port ISC_R2-RF10
ISC_R2-RF11: C123.N(OUT_5) ; port ISC_R2-RF11
ISC_R2-RF12: C123.N(OUT_6) ; port ISC_R2-RF12
ISC_R2-RF13: C123.N(OUT_8) ; port ISC_R2-RF13
ISC_R2-RF14: C124.N(OUT_1) C128.SMA(LOIN_1) ; port ISC_R2-RF14
ISC_R2-RF15: C124.N(OUT_2) C128.SMA(LOIN_3) ; port ISC_R2-RF15
ISC_R2-RF16: C124.N(OUT_3) ; port ISC_R2-RF16
ISC_R2-RF17: C124.N(OUT_4) ; port ISC_R2-RF17
ISC_R2-RF18: C124.N(OUT_5) ; port ISC_R2-RF18
ISC_R2-RF19: C124.N(OUT_7) C125.TNC(Input1) ; port ISC_R2-RF19
ISC_R2-RF20: C124.N(OUT_8) C125.TNC(Input2) ; port ISC_R2-RF20
ISC_R2-RF21: C125.TNC(Output1) C126.TNC(LO1) ; port ISC_R2-RF21
ISC_R2-RF22: C125.TNC(Output2) C126.TNC(LO2) ; port ISC_R2-RF22
ISC_R2-RF23: C126.SMA(RFOut1) C129.SMA(RF1_PD2) ; port ISC_R2-RF23
ISC_R2-RF24: C126.TNC(Q-1) ; port ISC_R2-RF24
ISC_R2-RF25: C126.SMA(RFIn2) ; port ISC_R2-RF25
ISC_R2-RF26: C126.TNC(I-1) ; port ISC_R2-RF26
ISC_R2-RF27: C126.TNC(I-2) ; port ISC_R2-RF27
ISC_R2-RF29: C128.SMA(RFIN1) C129.SMA(TestIN-1) ; port ISC_R2-RF29
ISC_R2-RF30: C128.SMA(RFIN2) C129.SMA(RF2_PD1) ; port ISC_R2-RF30
ISC_R2-RF31: C128.SMA(RFIN4) C129.SMA(RF2_PD2) ; port ISC_R2-RF31
ISC_R2-RF32: C129.SMA(RF1_PD3) C130.SMA(RFIN1) ; port ISC_R2-RF32
ISC_R2-RF33: C129.SMA(RF1_PD4) C130.SMA(RFIN2) C130_B.N(IN) ; port ISC_R2-RF33
ISC_R2-RF34: C130.SMA(RFIN3) C130_B.N(LF) ; port ISC_R2-RF34
ISC_R2-RF35: C130.SMA(RFIN4) C130_B.N(HF) ; port ISC_R2-RF35
ISC_Temp_10: C129.TNC(RF1_PD1) ; port ISC_Temp_10
ISC_Temp_15: C129.TNC(TestIN-2) ; port ISC_Temp_15
ISC_Temp_17: C129.TNC(RF1_PD2) ; port ISC_Temp_17
ISC_Temp_20: C129.TNC(RF2_PD1) ; port ISC_Temp_20
ISC_Temp_21: C129.TNC(TestIN-1) ; port ISC_Temp_21
ISC_Temp_22: C129.TNC(TestOut2) ; port ISC_Temp_22
ISC_Temp_A?: C129.TNC(TestOut1) ; port ISC_Temp_A?
ISC_Temp_B?: C129.TNC(RF1_PD3) ; port ISC_Temp_B?
ISC_Temp_C?: C129.TNC(RF1_PD4) ; port ISC_Temp_C?
ISC_X: C130_B.D25F(Controls) ; port ISC_X

Not connected (* = marked no-connect by the designer): C122 N(1)*; C123 BNC(M1)* Conec-3(DC+/-17)*; C124 BNC(M1)* Conec-3(DC+/-17)*; C125 Conec-3(DC+15)*; C126 BNC(I-Mon1)* Conec-3(DC+/-18)* D9F(DAQ)*; C127 Conec-3(DC+/-18)*; C128 BNC(I-Mon1)* Conec-3(DC+/-18)*; C130 BNC(I-Mon1)* Conec-3(DC+/-18)*; C130_B Conec-3(DC+/-17)*; C131 Conec-3(DC+/-18)*

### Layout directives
Length: X": ISC_R2-RF1, ISC_R2-RF2, ISC_R2-RF3, ISC_R2-RF4, ISC_R2-RF5, ISC_R2-RF6, ISC_R2-RF7, ISC_R2-RF8, ISC_R2-RF9, ISC_R2-RF10, ISC_R2-RF11, ISC_R2-RF12, ISC_R2-RF13, ISC_R2-RF14, ISC_R2-RF15, ISC_R2-RF16, ISC_R2-RF17, ISC_R2-RF18, ISC_R2-RF19, ISC_R2-RF20, ISC_R2-RF23, ISC_R2-RF24, ISC_R2-RF26, ISC_R2-RF27, ISC_R2-RF29, ISC_R2-RF30, ISC_R2-RF31, ISC_R2-RF32, ISC_R2-RF33, ISC_R2-RF34, ISC_R2-RF35
Length: 20ft: ISC_51, ISC_52, ISC_57, ISC_58, ISC_67
Length: 10": ISC_R2-RF21, ISC_R2-RF22
Length: 6ft: ISC_29, ISC_30

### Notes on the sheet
- ISC-R2 Rack
- (near C121) RF Patch Panel 13
- 9MHz
- 45MHz
- (near C123) 45MHz
- (near C124) 9MHz
- 18MHz
- 27MHz
- 90MHz
- 135MHz
- No Cable
- (near C122) RF Patch Panel 14
- Cable has Tee
- Goes to D1002559, U22
- and ISC-R4, U17
- To R4 Demod Conc
- LSC POPAIR A 9&45, LSC REFLAIR A 45
- LSC POPAIR B 18&90, LSC REFLAIR B 27&135
- Split cable
- R2_RF3 tied to TEE
- (near C130_B) Need to label & locate other end
- RFIN1 & RFIN2 are combined with a TEE

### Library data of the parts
C121 C122 = RF Dist. PatchPanel: Serial: Sxxxxxxx; System: ISC
C123 C124 = RF Distribution Amplifier: Serial: Sxxxxxxx; System: ISC
C125 = DelayLinePhaseShifter: Serial: Sxxxxxxx; System: ISC
C126 = 2-Chan Demod: Serial: Sxxxxxxx; System: ISC
C127 C131 = ISC Whitening: Serial: Sxxxxxxx
C128 C130 = QuadIQdemod_LSC: Serial: Sxxxxxxx; System: ISC
C129 = LSC RFPD PatchPanel: Serial: Sxxxxxxx; System: ISC
C130_B = RF Diplexer: Serial: Sxxxxxxx; System: ISC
